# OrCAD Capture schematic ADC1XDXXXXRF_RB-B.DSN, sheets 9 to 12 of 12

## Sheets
9 FPGA1: size C; block B7
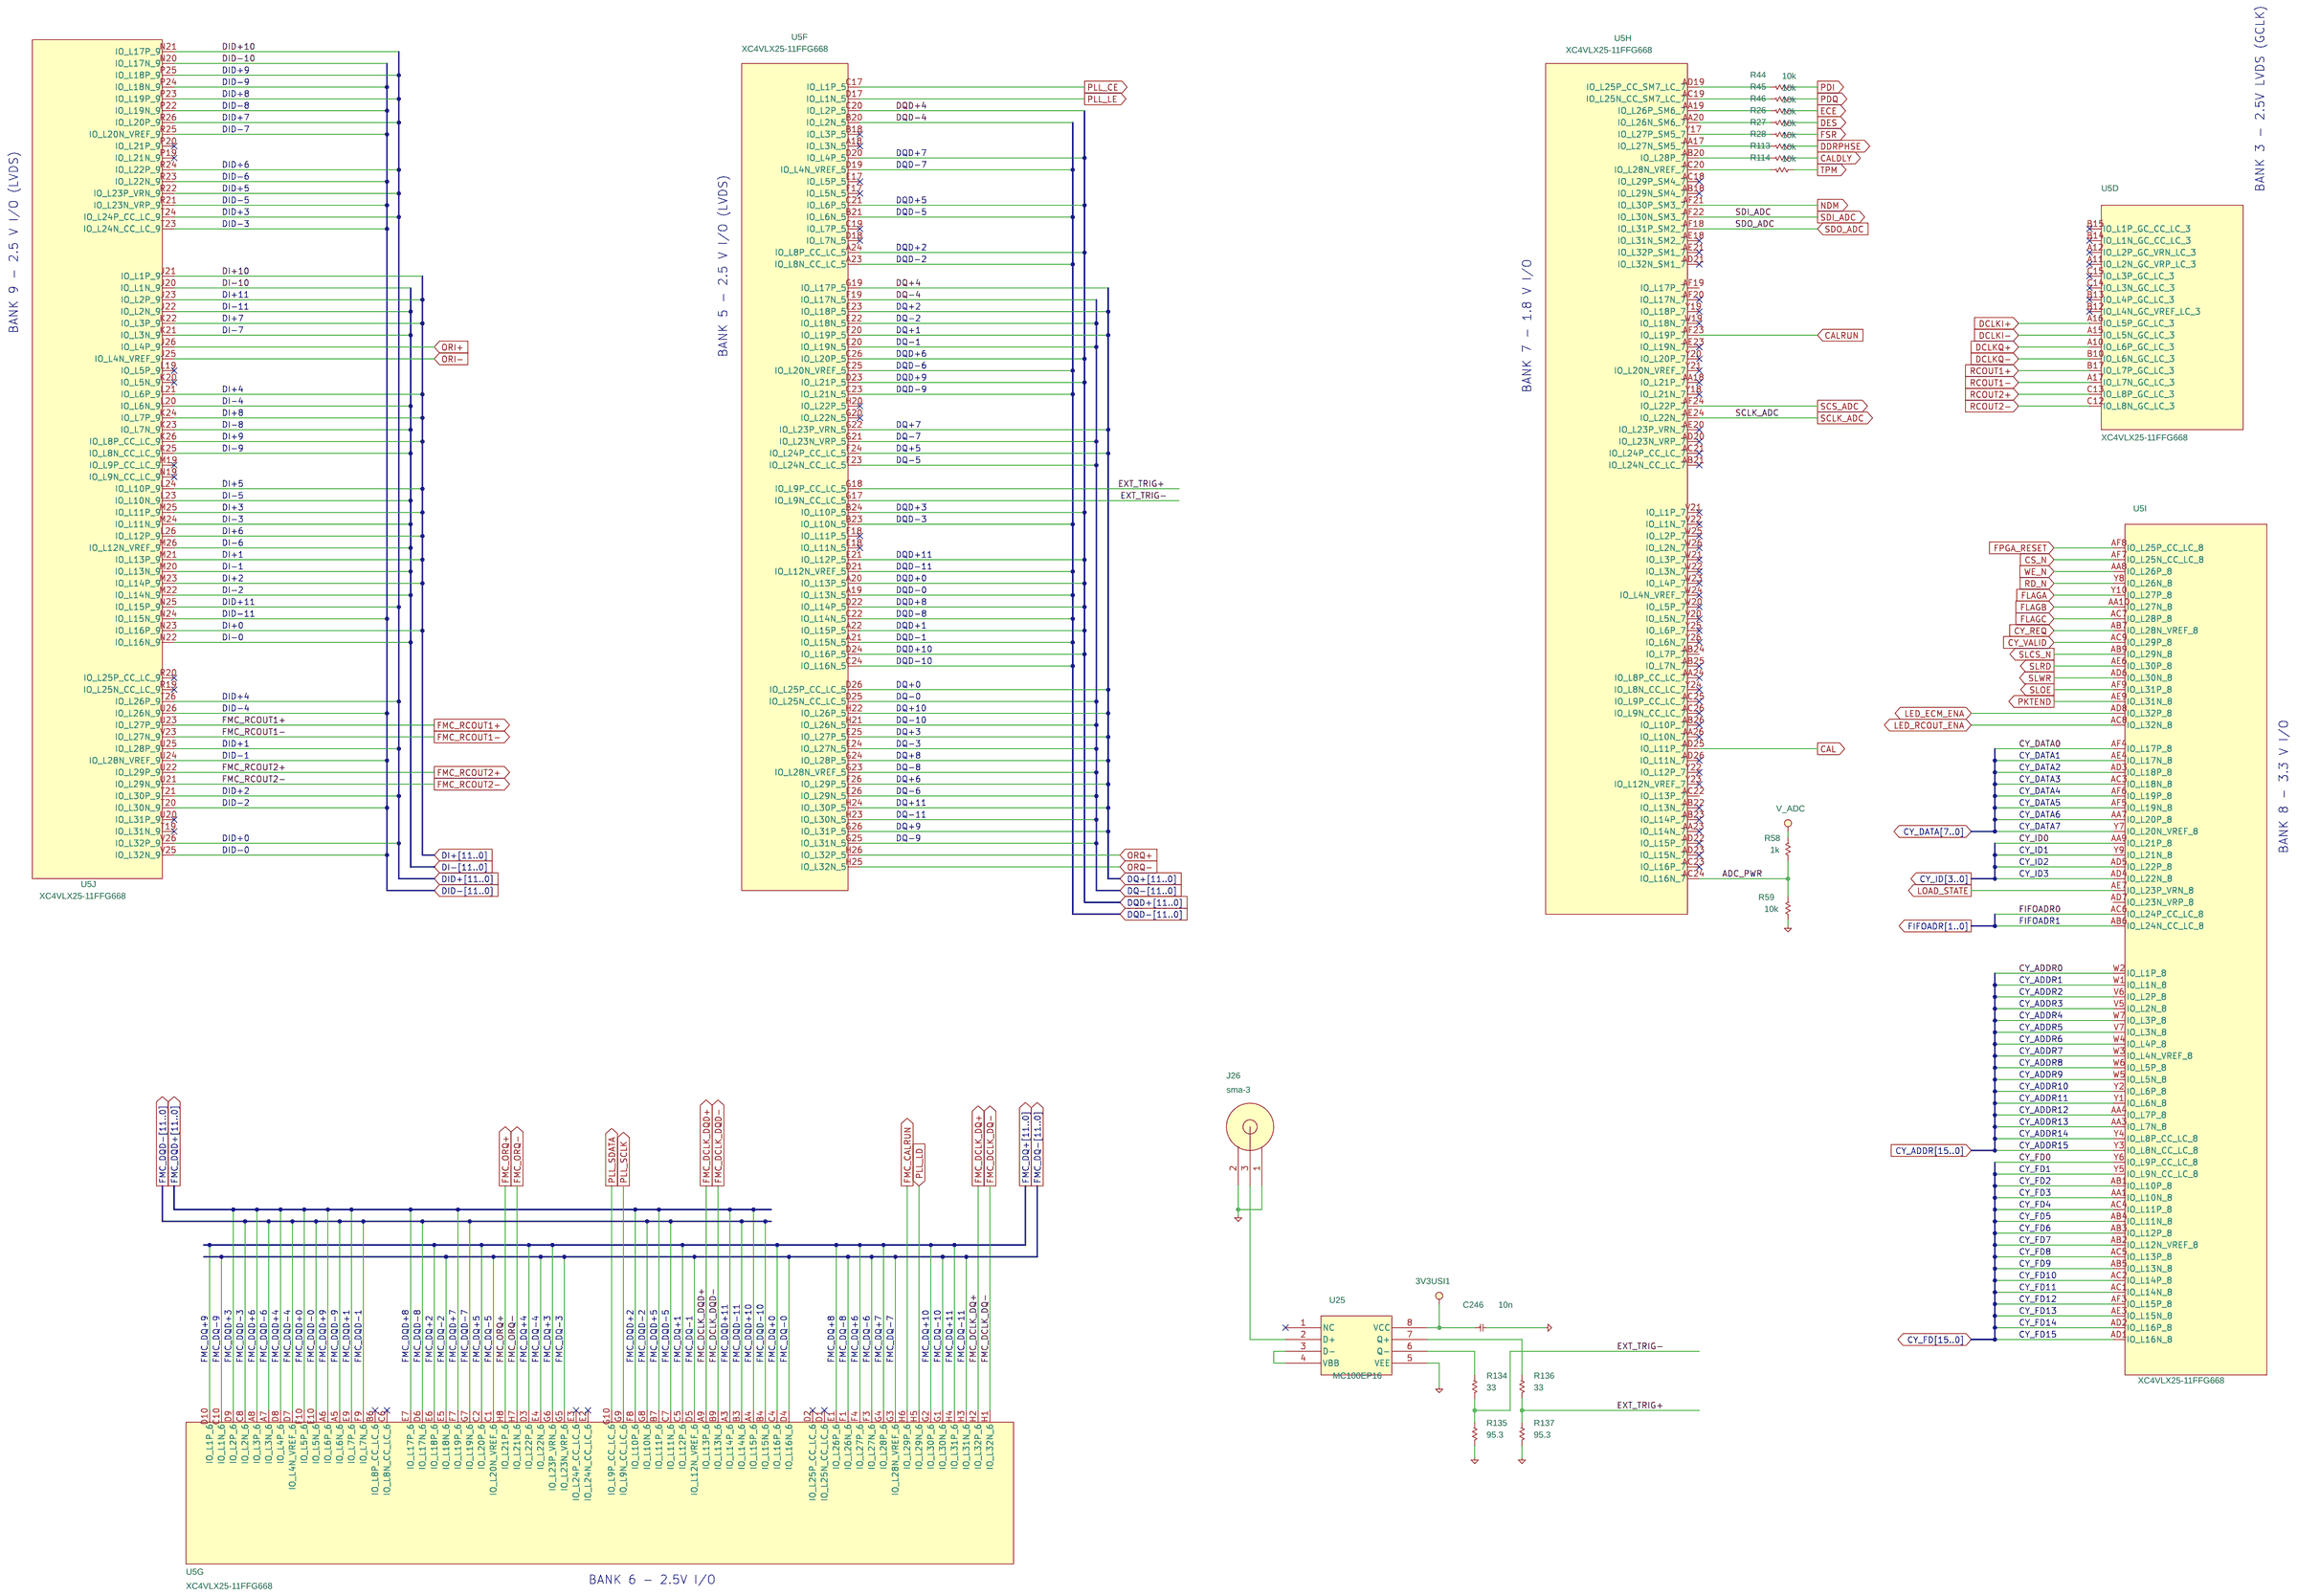
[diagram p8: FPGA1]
10 FPGA2: size C; block B7
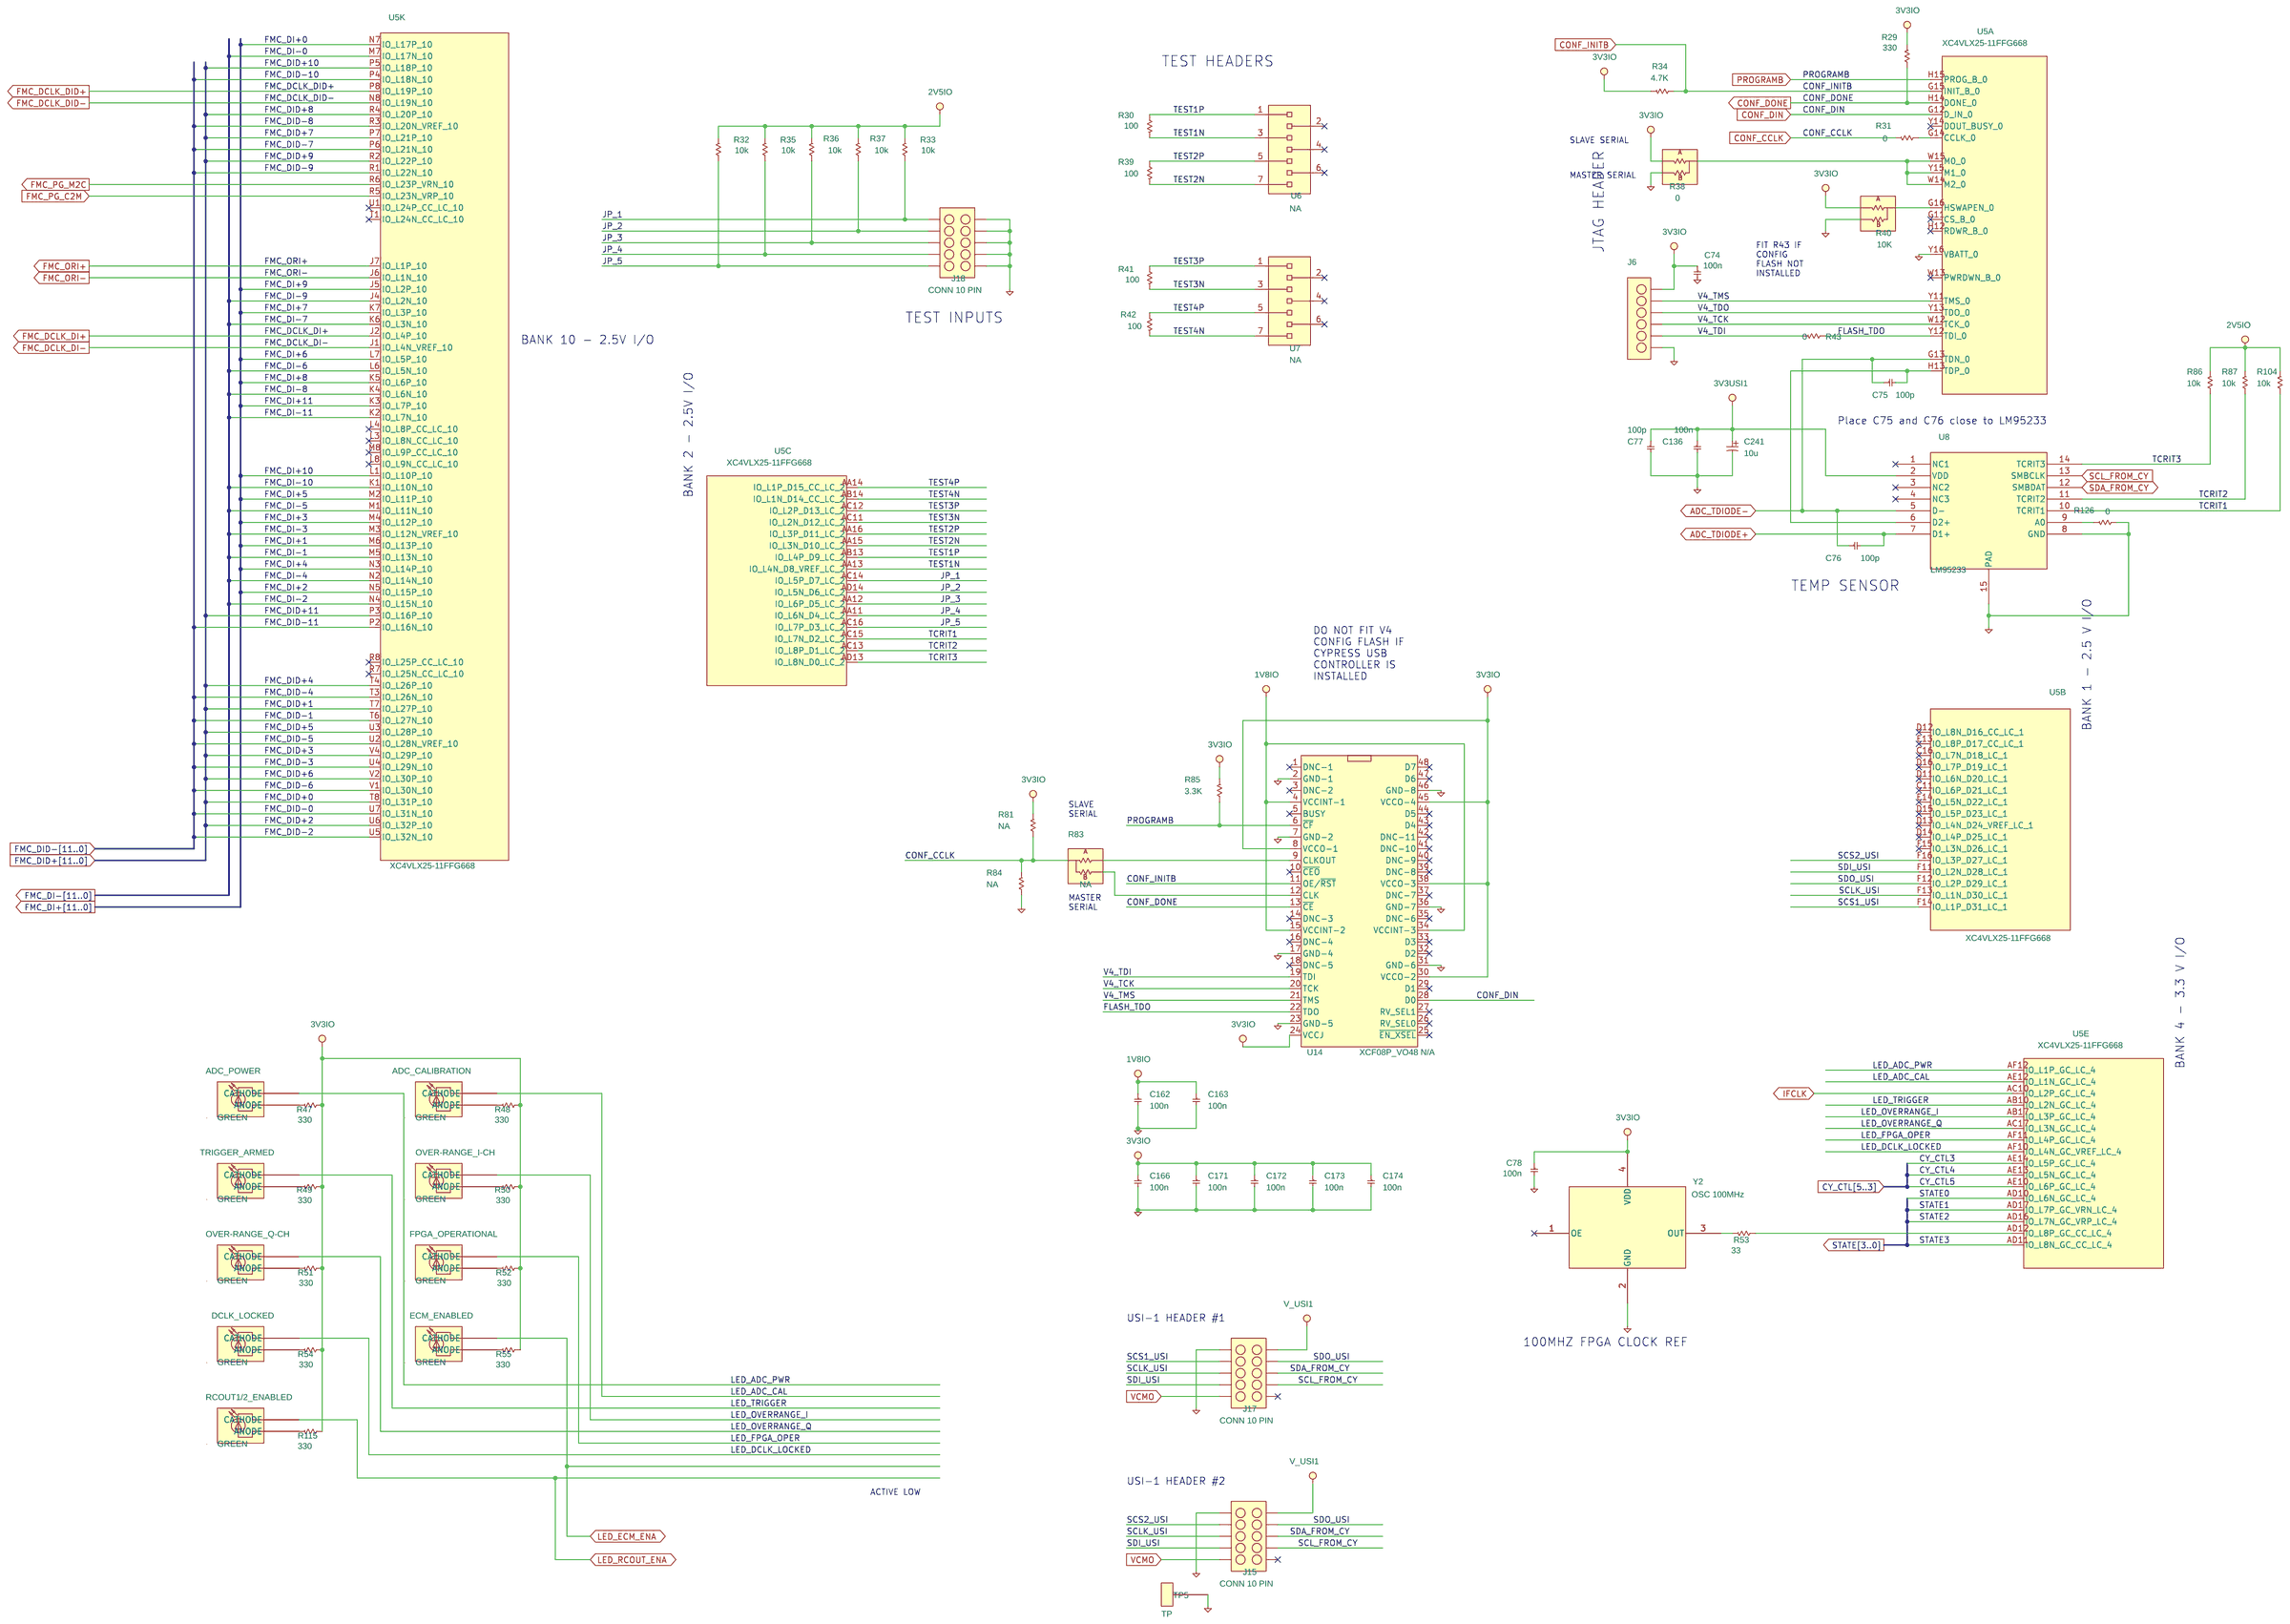
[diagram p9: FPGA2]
11 FPGA3: size C; block B7
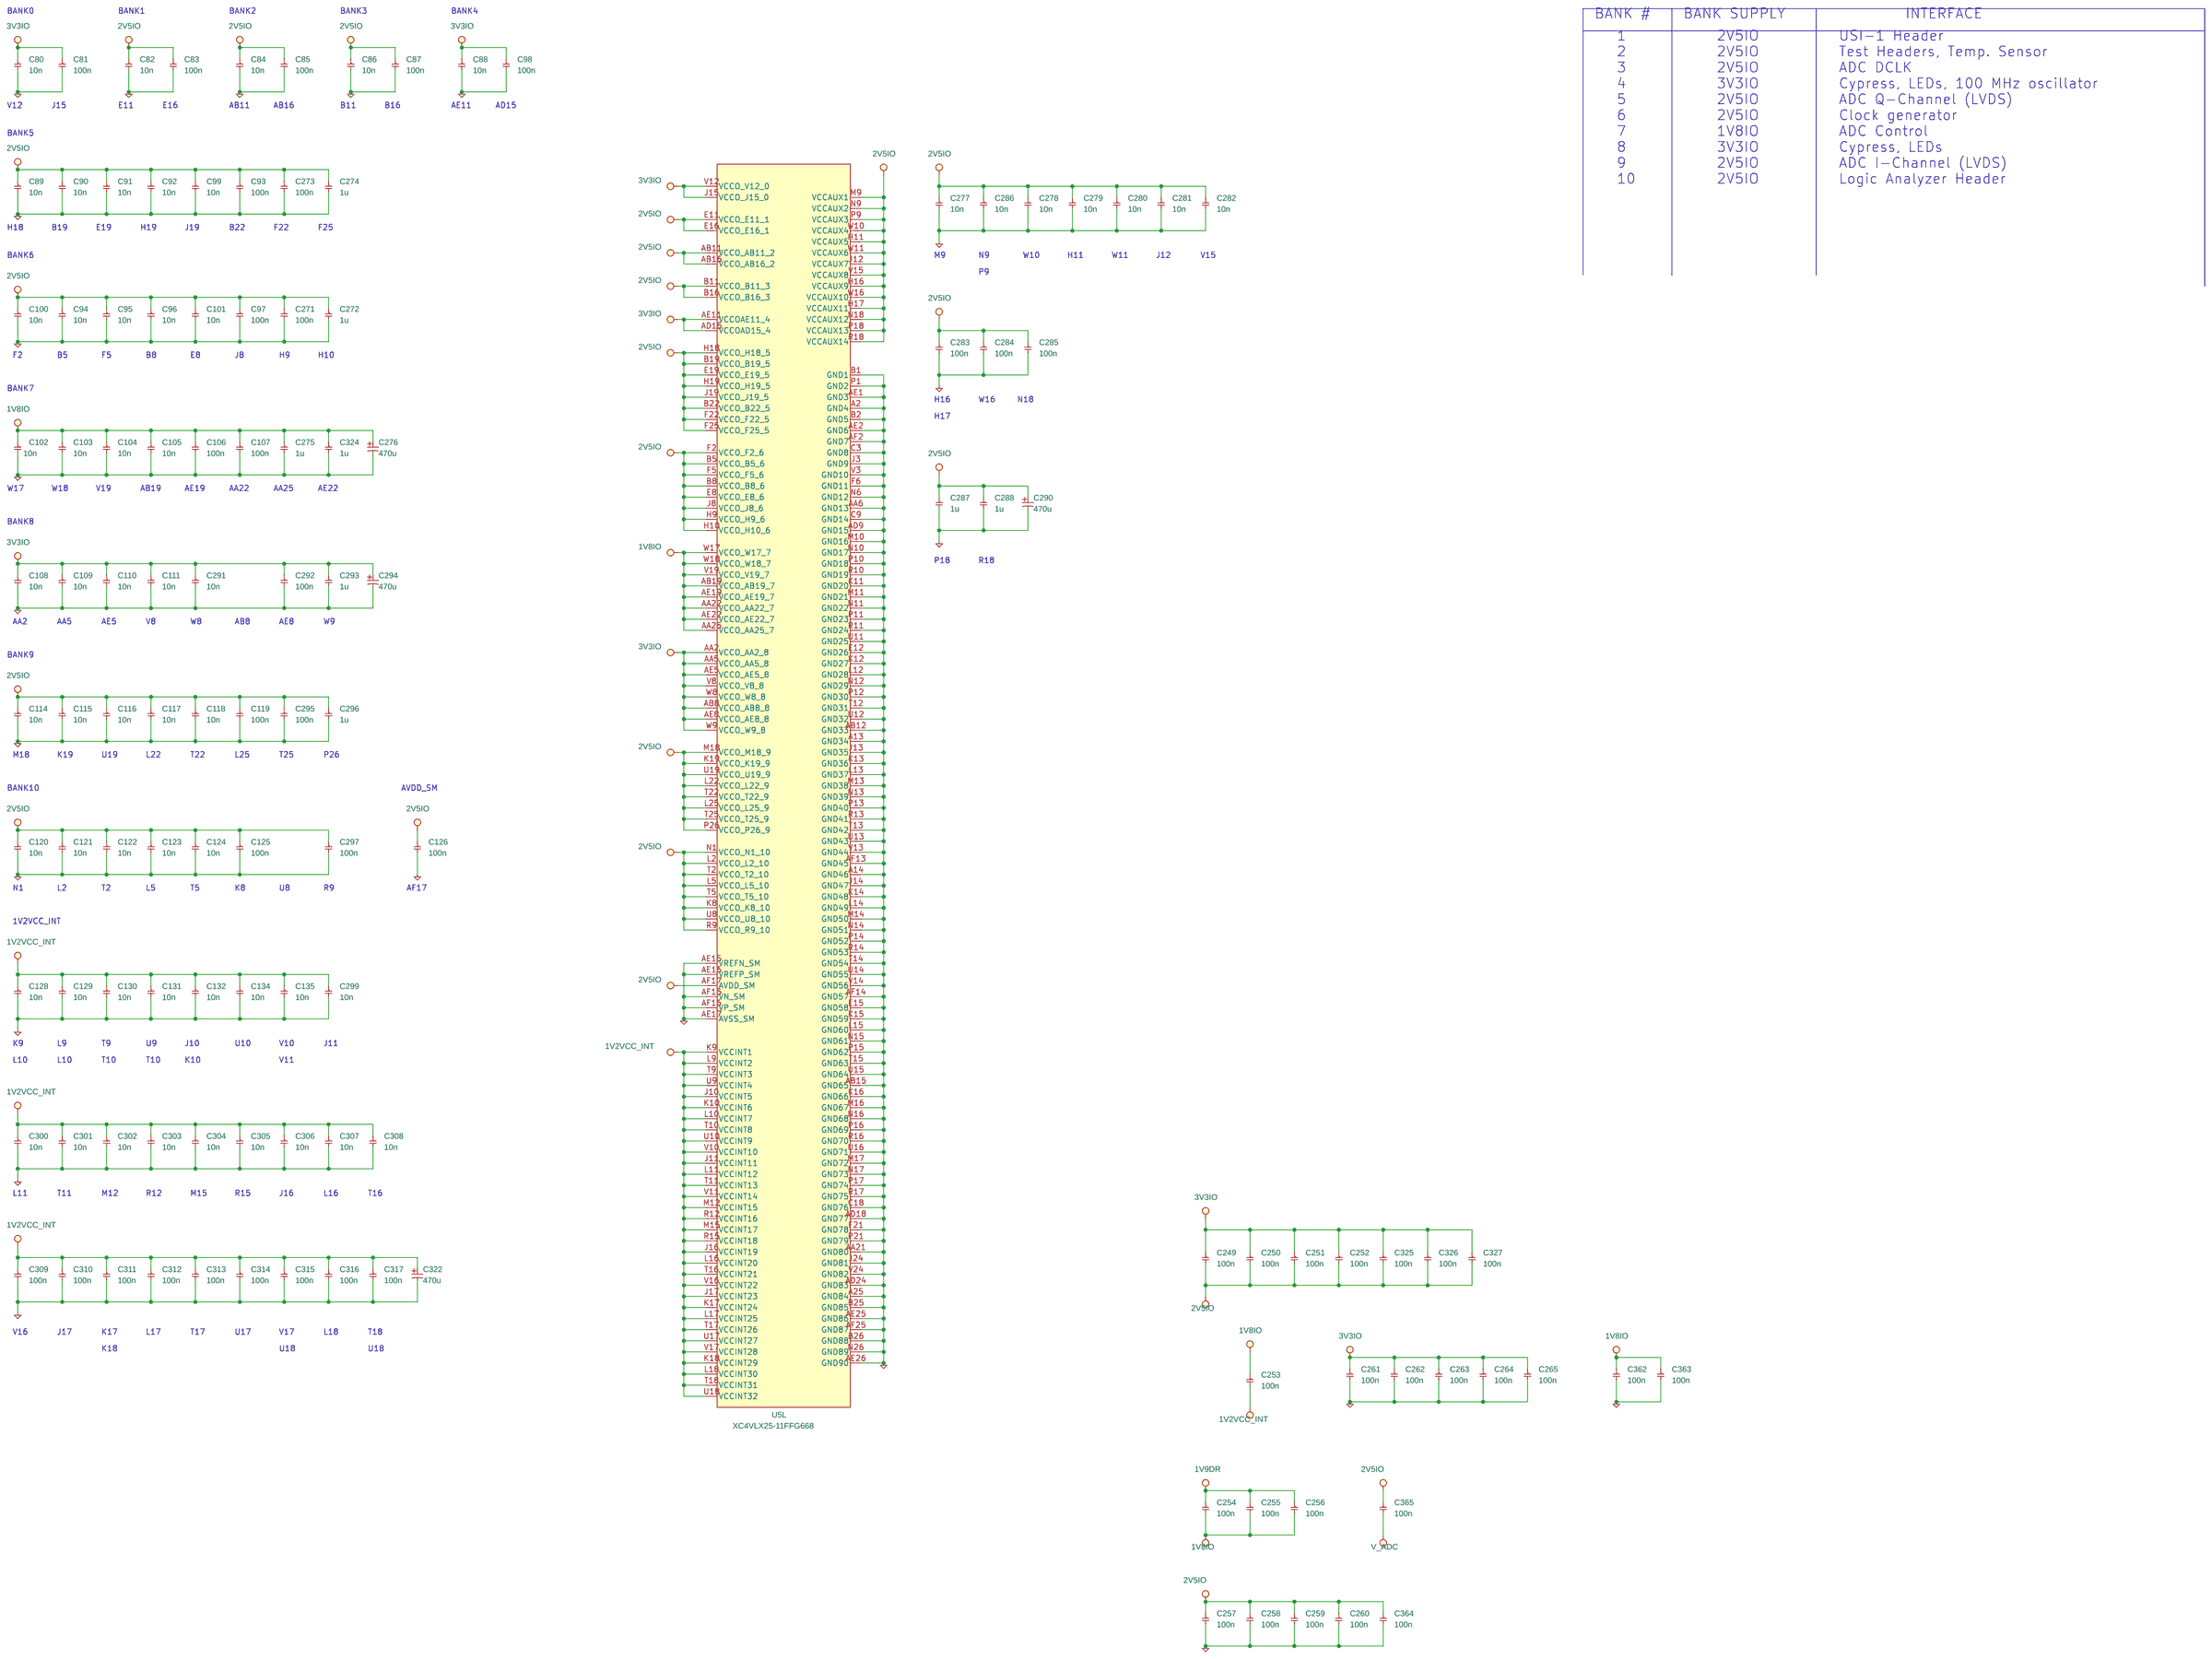
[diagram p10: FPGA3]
12 Front End: size C; block B6
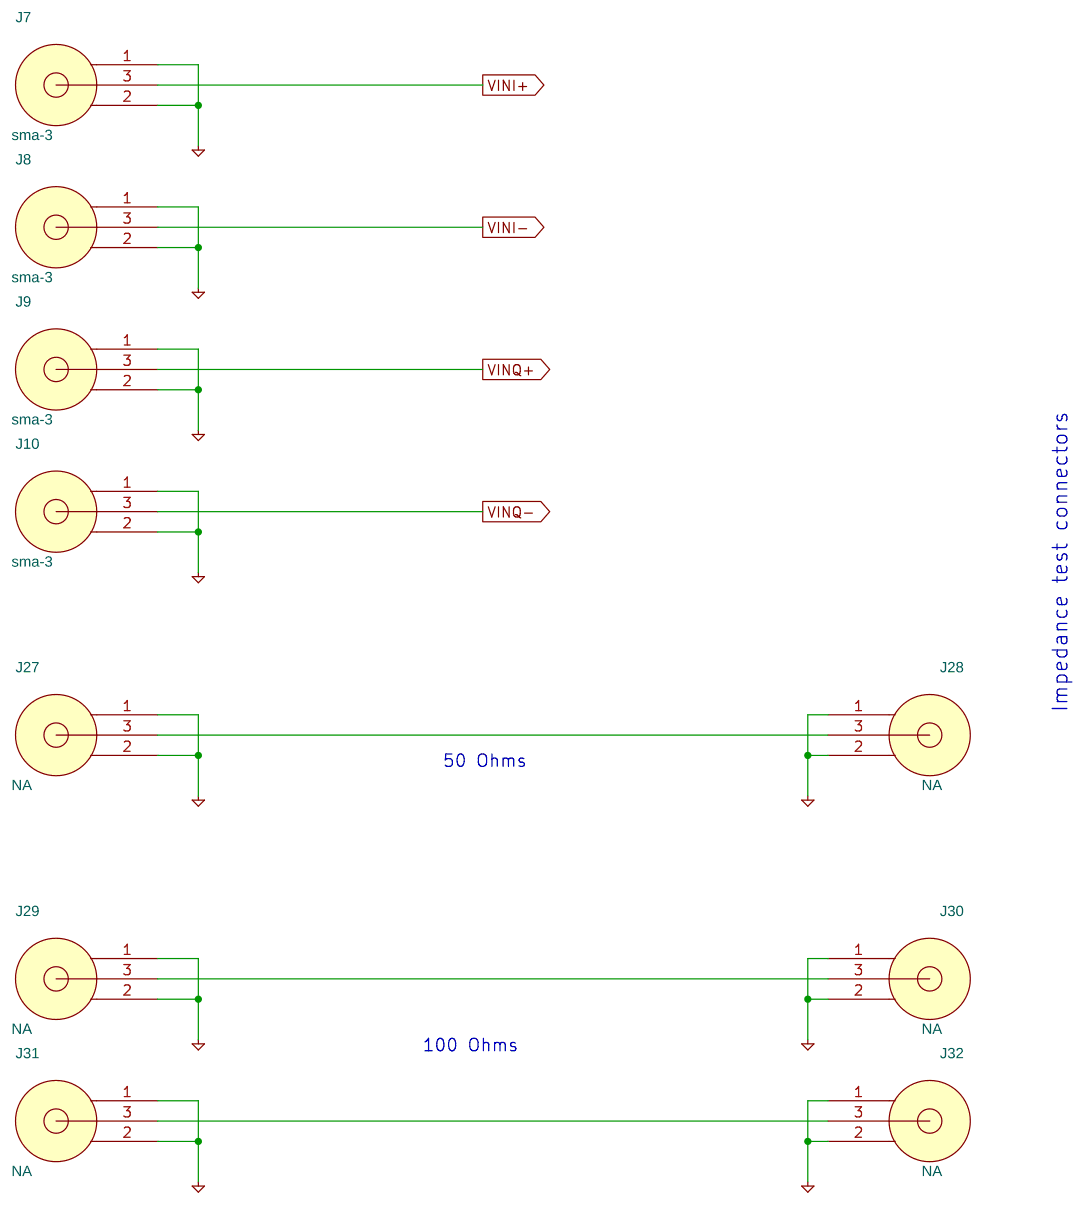
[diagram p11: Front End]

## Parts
sheet FPGA1
C246  10n  [c0402]
J26  sma-3  [RF_SMA_END_LAUNCH]
R26  10k  [r0603]
R27  10k  [r0603]
R28  10k  [r0603]
R44  10k  [r0603]
R45  10k  [r0603]
R46  10k  [r0603]
R58  1k  [r0603]
R59  10k  [r0603]
R113  10k  [r0603]
R114  10k  [r0603]
R134  33  [r0603]
R135  95.3  [r0603]
R136  33  [r0603]
R137  95.3  [r0603]
U5  XC4VLX25-11FFG668  [bga_668_27x27_1p0]  (sections A,B,C,D,E,F,G,H,I,J,K,L)
U25  MC100EP16  [TSSOP8_65M_WG4P9_L3]
sheet FPGA2
ADC_CALIBRATION  GREEN  [r1206]
ADC_POWER  GREEN  [r1206]
C74  100n  [c0603]
C75  100p  [c0402]
C76  100p  [c0402]
C77  100p  [c0402]
C78  100n  [c0603]
C136  100n  [c0603]
C162  100n  [c0603]
C163  100n  [c0603]
C166  100n  [c0603]
C171  100n  [c0603]
C172  100n  [c0603]
C173  100n  [c0603]
C174  100n  [c0603]
C241  10u  [c0805]
DCLK_LOCKED  GREEN  [r1206]
ECM_ENABLED  GREEN  [r1206]
FPGA_OPERATIONAL  GREEN  [r1206]
J6  CONN 6 PIN SINGLE ROW  [SHDR6X1]
J15  CONN 10 PIN  [th_10_hdr2x5_m_str_100]
J17  CONN 10 PIN  [th_10_hdr2x5_m_str_100]
J18  CONN 10 PIN  [th_10_hdr2x5_m_str_100]
OVER-RANGE_I-CH  GREEN  [r1206]
OVER-RANGE_Q-CH  GREEN  [r1206]
R29  330  [r0603]
R30  100  [r0603]
R31  0  [r0603]
R32  10k  [r0603]
R33  10k  [r0603]
R34  4.7K  [r0603]
R35  10k  [r0603]
R36  10k  [r0603]
R37  10k  [r0603]
R38  0  [0603_TRIPAD_1_to_2]
R39  100  [r0603]
R40  10K  [0603_TRIPAD_1_to_2]
R41  100  [r0603]
R42  100  [r0603]
R43  0  [r0603]
R47  330  [r0603]
R48  330  [r0603]
R49  330  [r0603]
R50  330  [r0603]
R51  330  [r0603]
R52  330  [r0603]
R53  33  [r0603]
R54  330  [r0603]
R55  330  [r0603]
R81  NA  [r0603]
R83  NA  [0603_TRIPAD]
R84  NA  [r0603]
R85  3.3K  [r0603]
R86  10k  [r0603]
R87  10k  [r0603]
R104  10k  [r0603]
R115  330  [r0603]
R126  0  [r0603]
RCOUT1/2_ENABLED  GREEN  [r1206]
TP5  TP  [tp40]
TRIGGER_ARMED  GREEN  [r1206]
U6  NA  [sm_7pin_ftr]
U7  NA  [sm_7pin_ftr]
U8  LM95233  [LLP14_p5mm_4x4_ep]
U14  XCF08P_VO48 N/A  [TSSOP48_50M_WG20_L12]
Y2  OSC 100MHz  [osc_100m_5x7]
sheet FPGA3
C80  10n  [c0402_no_ss]
C81  100n  [c0402_no_ss]
C82  10n  [c0402_no_ss]
C83  100n  [c0402_no_ss]
C84  10n  [c0402_no_ss]
C85  100n  [c0402_no_ss]
C86  10n  [c0402_no_ss]
C87  100n  [c0402_no_ss]
C88  10n  [c0402_no_ss]
C89  10n  [c0402_no_ss]
C90  10n  [c0402_no_ss]
C91  10n  [c0402_no_ss]
C92  10n  [c0402_no_ss]
C93  100n  [c0402_no_ss]
C94  10n  [c0402_no_ss]
C95  10n  [c0402_no_ss]
C96  10n  [c0402_no_ss]
C97  100n  [c0402_no_ss]
C98  100n  [c0402_no_ss]
C99  10n  [c0402_no_ss]
C100  10n  [c0402_no_ss]
C101  10n  [c0402_no_ss]
C102  10n  [c0402_no_ss]
C103  10n  [c0402_no_ss]
C104  10n  [c0402_no_ss]
C105  10n  [c0402_no_ss]
C106  100n  [c0402_no_ss]
C107  100n  [c0402_no_ss]
C108  10n  [c0402_no_ss]
C109  10n  [c0402_no_ss]
C110  10n  [c0402_no_ss]
C111  10n  [c0402_no_ss]
C114  10n  [c0402_no_ss]
C115  10n  [c0402_no_ss]
C116  10n  [c0402_no_ss]
C117  10n  [c0402_no_ss]
C118  10n  [c0402_no_ss]
C119  100n  [c0402_no_ss]
C120  10n  [c0402_no_ss]
C121  10n  [c0402_no_ss]
C122  10n  [c0402_no_ss]
C123  10n  [c0402_no_ss]
C124  10n  [c0402_no_ss]
C125  100n  [c0402_no_ss]
C126  100n  [c0402_no_ss]
C128  10n  [c0402_no_ss]
C129  10n  [c0402_no_ss]
C130  10n  [c0402_no_ss]
C131  10n  [c0402_no_ss]
C132  10n  [c0402_no_ss]
C134  10n  [c0402_no_ss]
C135  10n  [c0402_no_ss]
C249  100n  [c0402]
C250  100n  [c0402]
C251  100n  [c0402]
C252  100n  [c0402]
C253  100n  [c0402_no_ss]
C254  100n  [c0402]
C255  100n  [c0402]
C256  100n  [c0402]
C257  100n  [c0402]
C258  100n  [c0402]
C259  100n  [c0402]
C260  100n  [c0402_no_ss]
C261  100n  [c0402]
C262  100n  [c0402]
C263  100n  [c0402]
C264  100n  [c0402]
C265  100n  [c0402]
C271  100n  [c0402_no_ss]
C272  1u  [c0402_no_ss]
C273  100n  [c0402_no_ss]
C274  1u  [c0402_no_ss]
C275  1u  [c0402_no_ss]
C276  470u  [cap_c-case]
C277  10n  [c0402_no_ss]
C278  10n  [c0402_no_ss]
C279  10n  [c0402_no_ss]
C280  10n  [c0402_no_ss]
C281  10n  [c0402_no_ss]
C282  10n  [c0402_no_ss]
C283  100n  [c0402_no_ss]
C284  100n  [c0402_no_ss]
C285  100n  [c0402_no_ss]
C286  10n  [c0402_no_ss]
C287  1u  [c0402_no_ss]
C288  1u  [c0402_no_ss]
C290  470u  [cap_c-case]
C291  10n  [c0402_no_ss]
C292  100n  [c0402_no_ss]
C293  1u  [c0402_no_ss]
C294  470u  [cap_c-case]
C295  100n  [c0402_no_ss]
C296  1u  [c0402_no_ss]
C297  100n  [c0402_no_ss]
C299  10n  [c0402_no_ss]
C300  10n  [c0402_no_ss]
C301  10n  [c0402_no_ss]
C302  10n  [c0402_no_ss]
C303  10n  [c0402_no_ss]
C304  10n  [c0402_no_ss]
C305  10n  [c0402_no_ss]
C306  10n  [c0402_no_ss]
C307  10n  [c0402_no_ss]
C308  10n  [c0402_no_ss]
C309  100n  [c0402_no_ss]
C310  100n  [c0402_no_ss]
C311  100n  [c0402_no_ss]
C312  100n  [c0402_no_ss]
C313  100n  [c0402_no_ss]
C314  100n  [c0402_no_ss]
C315  100n  [c0402_no_ss]
C316  100n  [c0402_no_ss]
C317  100n  [c0402_no_ss]
C322  470u  [cap_c-case]
C324  1u  [c0402_no_ss]
C325  100n  [c0402]
C326  100n  [c0402]
C327  100n  [c0402]
C362  100n  [c0402]
C363  100n  [c0402]
C364  100n  [c0402_no_ss]
C365  100n  [c0402_no_ss]
sheet Front End
J7  sma-3  [RF_SMA_END_LAUNCH]
J8  sma-3  [RF_SMA_END_LAUNCH]
J9  sma-3  [RF_SMA_END_LAUNCH]
J10  sma-3  [RF_SMA_END_LAUNCH]
J27  NA  [RF_SMA_END_LAUNCH]
J28  NA  [RF_SMA_END_LAUNCH]
J29  NA  [RF_SMA_END_LAUNCH]
J30  NA  [RF_SMA_END_LAUNCH]
J31  NA  [RF_SMA_END_LAUNCH]
J32  NA  [RF_SMA_END_LAUNCH]

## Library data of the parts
C80 C82 C84 C86 C88-C92 C94-C96 C99-C105 C108-C111 C114-C118 C120-C124 C128-C132 C134 C135 C246 C277-C282 C286 C291 C299-C308 = C-NON-POL: Distributed by: Digikey; Distributor Part #: 445-1260-1-ND; Manufactured by: TDK Corporation; Part Description: CAP CER 10000PF 25V 10% X7R 0402; Part Number: C1005X7R1E103K
J7-J10 J26 = sma-3_0: Distributed by: Digikey; Distributor Part #: J658-ND; Manufactured by: Emerson Network Power Connectivity Solutions; Part Description: CONN JACK END LAUNCH PC GOLD SMA; Part Number: 142-0701-851
R26-R28 R32 R33 R35-R37 R44-R46 R59 R86 R87 R104 R113 R114 = RESISTOR: Distributed by: Digikey; Distributor Part #: P10KGCT-ND; Manufactured by: Panasonic; Part Description: RES 10K OHM 1/10W 5% 0603 SMD; Part Number: ERJ-3GEYJ103V
R58 = RESISTOR: Distributed by: Digikey; Distributor Part #: P1.0KGCT-ND; Manufactured by: Panasonic; Part Description: RES 1.0K OHM 1/10W 5% 0603 SMD; Part Number: ERJ-3GEYJ102V
R53 R134 R136 = RESISTOR: Distributed by: Digikey; Distributor Part #: P33GCT-ND; Manufactured by: Panasonic; Part Description: RES 33 OHM 1/10W 5% 0603 SMD; Part Number: ERJ-3GEYJ330V
R135 R137 = RESISTOR: Distributed by: Digikey; Distributor Part #: P95.3HCT-ND; Manufactured by: Panasonic; Part Description: RES 95.3 OHM 1/10W 1% 0603 SMD; Part Number: ERJ-3EKF95R3V
U5 = XC4VLX25-11FFG668__3: Distributed by: NuHorizons; Manufactured by: Xilinx; Part Description: FPGA VIRTEX-4 FG668 -11
U25 = MC10EP16: Distributed by: Digikey; Distributor Part #: MC100EP16DTGOS-ND; Manufactured by: On Semiconductor; Part Description: IC RCVR/DRVR ECL DIFF 5V 8TSSOP; Part Number: MC100EP16DTG
ADC_CALIBRATION ADC_POWER DCLK_LOCKED ECM_ENABLED FPGA_OPERATIONAL OVER-RANGE_I-CH OVER-RANGE_Q-CH RCOUT1/2_ENABLED TRIGGER_ARMED = LED_SNGLE_PANEL: Distributed by: Digikey; Distributor Part #: 67-1357-1-ND; Manufactured by: Lumex; Part Description: LED 565NM WTR CLR GREEN 1206 SMD; Part Number: SML-LX1206GC-TR
C74 C78 C136 C162 C163 C166 C171-C174 = C-NON-POL: Distributed by: Digikey; Distributor Part #: 445-1317-1-ND; Manufactured by: TDK Corporation; Part Description: CAP CER 0.1UF 16V 10% X7R 0603; Part Number: C1608X7R1C104K
C75-C77 = C-NON-POL: Distributed by: Digikey; Distributor Part #: 399-3194-1-ND; Manufactured by: Kemet; Part Description: CAP CER 100PF 50V 5% NP0 0402; Part Number: C0402C101J5GACTU
C241 = C-POLARISED: Distributed by: Digikey; Distributor Part #: 445-1363-2-ND; Manufactured by: TDK; Part Description: CAP CER 10UF 6.3V 20% X5R 0805; Part Number: C2012X5R0J106M/1.25
J6 = CONN_6_PIN_SINGLE_ROW: Comment: BROKEN TO SIZE; Distributed by: Digikey; Distributor Part #: S1012E-36-ND; Manufactured by: Sullins Connector Solutions; Part Description: CONN HEADER .100 SINGL STR 36POS; Part Number: PEC36SAAN
J15 J17 J18 = CONN_10_PIN_2mm_SMT_DUAL_ROW: Comment: BROKEN TO SIZE; Distributed by: Digikey; Distributor Part #: S2012E-36-ND; Manufactured by: Sullins Connector Solutions; Part Description: CONN HEADER .100 DUAL STR 72POS; Part Number: PEC36DAAN
R29 R47-R52 R54 R55 R115 = RESISTOR: Distributed by: Digikey; Distributor Part #: P330GTR-ND; Manufactured by: Panasonic; Part Description: RES 330 OHM 1/10W 5% 0603 SMD; Part Number: ERJ-3GEYJ331V
R30 R39 R41 R42 = RESISTOR: Distributed by: Digikey; Distributor Part #: P100GCT-ND; Manufactured by: Panasonic; Part Description: RES 100 OHM 1/10W 5% 0603 SMD; Part Number: ERJ-3GEYJ101V
R31 R43 R126 = RESISTOR: Distributed by: Digikey; Distributor Part #: P0.0GCT-ND; Manufactured by: Panasonic; Part Description: RES 0 OHM 1/10W 5% 0603 SMD; Part Number: ERJ-3GEY0R00V
R34 = RESISTOR: Distributed by: Digikey; Distributor Part #: P4.7KGCT-ND; Manufactured by: Panasonic; Part Description: RES 4.7K OHM 1/10W 5% 0603 SMD; Part Number: ERJ-3GEYJ472V
R38 = RESISTOR_TRIPAD: Distributed by: Digikey; Distributor Part #: P0.0GTR-ND; Manufactured by: Panasonic; Part Description: RES 0 OHM 1/10W 5% 0603 SMD; Part Number: ERJ-3GEY0R00V
R40 = RESISTOR_TRIPAD: Distributed by: Digikey; Distributor Part #: P10KGTR-ND; Manufactured by: Panasonic; Part Description: RES 10K OHM 1/10W 5% 0603 SMD; Part Number: ERJ-3GEYJ103V
R81 R84 = RESISTOR
R83 = RESISTOR_TRIPAD
R85 = RESISTOR: Distributed by: Digikey; Distributor Part #: P3.3KGTR-ND; Manufactured by: Panasonic; Part Description: RES 3.3K OHM 1/10W 5% 0603 SMD; Part Number: ERJ-3GEYJ332V
TP5 = TEST_POINT: Comment: BROKEN TO SIZE; Distributed by: Digikey; Distributor Part #: S1012E-36-ND; Manufactured by: Sullins Connector Solutions; Part Description: CONN HEADER .100 SINGL STR 36POS; Part Number: PEC36SAAN
U6 U7 = 2MM_7PIN_HEADER
U8 = LM95233: Distributed by: Digikey; Distributor Part #: LM95233CISDCT-ND; Manufactured by: Texas Instruments; Part Description: IC TEMP SENSOR DUAL REMOTE 14LLP; Part Number: LM95233CISD/NOPB
U14 = XCF08P_VO48_1: Manufactured by: Xilinx; Part Description: Xilinx Configuration Flash ROM (8Mb) JTAG; Part Number: XCF08P VO48 C
Y2 = OSC-SM: Distributed by: Pletronics; Distributor Part #: SM7745DSV-100.00M; Manufactured by: Pletronics; Part Description: OSC CLOCK 100.0000 MHZ 3.3V SMD; Part Number: SM7745DSV-100.00M
C81 C83 C85 C87 C93 C97 C98 C106 C107 C119 C125 C126 C253 C271 C273 C283-C285 C292 C295 C297 C309-C317 = C-NON-POL: Distributed by: Digikey; Distributor Part #: PCC2146TR-ND; Manufactured by: Panasonic; Part Description: Capacitor, SMT 0402, MLC, X5R, 10%, 10V; Part Number: ECJ-0EB1A104K
C249-C252 C254-C265 C325-C327 C362-C365 = C-NON-POL: Distributed by: Digikey; Distributor Part #: 478-1129-1-ND; Manufactured by: AVX Corporation; Part Description: CAP CER 0.1UF 10% 10V X5R 0402; Part Number: 0402ZD104KAT2A
C272 C274 C275 C287 C288 C293 C296 C324 = C-NON-POL: Distributed by: Digikey; Distributor Part #: 399-4873-1-ND; Manufactured by: Kemet; Part Description: CAP CER 1UF 6.3V 10% X5R 0402; Part Number: C0402C105K9PACTU
C276 C290 C294 C322 = C-POLARISED: Distributed by: Digikey; Distributor Part #: 478-4772-1-ND; Manufactured by: AVX Corporation; Part Description: CAP TANT 470UF 4V 10% 2312; Part Number: TAJC477K004RNJ
J27-J32 = sma-3_0

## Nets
1V2VCC_INT: C128.1 C129.1 C130.1 C131.1 C132.1 C134.1 C135.1 C253.2 C299.1 C300.1 C301.1 C302.1 C303.1 C304.1 C305.1 C306.1 C307.1 C308.1 C309.1 C310.1 C311.1 C312.1 C313.1 C314.1 C315.1 C316.1 C317.1 C322.1(POS) U5.J10(VCCINT5) U5.J11(VCCINT11) U5.J16(VCCINT19) U5.J17(VCCINT23) U5.K9(VCCINT1) U5.K10(VCCINT6) U5.K17(VCCINT24) U5.K18(VCCINT29) U5.L9(VCCINT2) U5.L10(VCCINT7) U5.L11(VCCINT12) U5.L16(VCCINT20) U5.L17(VCCINT25) U5.L18(VCCINT30) U5.M12(VCCINT15) U5.M15(VCCINT17) U5.R12(VCCINT16) U5.R15(VCCINT18) U5.T9(VCCINT3) U5.T10(VCCINT8) U5.T11(VCCINT13) U5.T16(VCCINT21) U5.T17(VCCINT26) U5.T18(VCCINT31) U5.U9(VCCINT4) U5.U10(VCCINT9) U5.U17(VCCINT27) U5.U18(VCCINT32) U5.V10(VCCINT10) U5.V11(VCCINT14) U5.V16(VCCINT22) U5.V17(VCCINT28) ; also on sheet 6
1V8IO: C102.1 C103.1 C104.1 C105.1 C106.1 C107.1 C162.1 C163.1 C253.1 C254.2 C255.2 C256.2 C275.1 C276.1(POS) C324.1 C362.1 C363.1 U5.AA22(VCCO_AA22_7) U5.AA25(VCCO_AA25_7) U5.AB19(VCCO_AB19_7) U5.AE19(VCCO_AE19_7) U5.AE22(VCCO_AE22_7) U5.V19(VCCO_V19_7) U5.W17(VCCO_W17_7) U5.W18(VCCO_W18_7) U14.4(VCCINT-1) U14.15(VCCINT-2) U14.34(VCCINT-3) ; also on sheet 3 6
1V9DR: C254.1 C255.1 C256.1 ; also on sheet 3
2V5IO: C82.1 C83.1 C84.1 C85.1 C86.1 C87.1 C89.1 C90.1 C91.1 C92.1 C93.1 C94.1 C95.1 C96.1 C97.1 C99.1 C100.1 C101.1 C114.1 C115.1 C116.1 C117.1 C118.1 C119.1 C120.1 C121.1 C122.1 C123.1 C124.1 C125.1 C126.1 C249.2 C250.2 C251.2 C252.2 C257.1 C258.1 C259.1 C260.1 C271.1 C272.1 C273.1 C274.1 C277.1 C278.1 C279.1 C280.1 C281.1 C282.1 C283.1 C284.1 C285.1 C286.1 C287.1 C288.1 C290.1(POS) C295.1 C296.1 C297.1 C325.2 C326.2 C327.2 C364.1 C365.1 R32.1 R33.1 R35.1 R36.1 R37.1 R86.1 R87.1 R104.1 U5.AB11(VCCO_AB11_2) U5.AB16(VCCO_AB16_2) U5.AF17(AVDD_SM) U5.B5(VCCO_B5_6) U5.B8(VCCO_B8_6) U5.B11(VCCO_B11_3) U5.B16(VCCO_B16_3) U5.B19(VCCO_B19_5) U5.B22(VCCO_B22_5) U5.E8(VCCO_E8_6) U5.E11(VCCO_E11_1) U5.E16(VCCO_E16_1) U5.E19(VCCO_E19_5) U5.F2(VCCO_F2_6) U5.F5(VCCO_F5_6) U5.F22(VCCO_F22_5) U5.F25(VCCO_F25_5) U5.H9(VCCO_H9_6) U5.H10(VCCO_H10_6) U5.H11(VCCAUX5) U5.H16(VCCAUX9) U5.H17(VCCAUX11) U5.H18(VCCO_H18_5) U5.H19(VCCO_H19_5) U5.J8(VCCO_J8_6) U5.J12(VCCAUX7) U5.J19(VCCO_J19_5) U5.K8(VCCO_K8_10) U5.K19(VCCO_K19_9) U5.L2(VCCO_L2_10) U5.L5(VCCO_L5_10) U5.L22(VCCO_L22_9) U5.L25(VCCO_L25_9) U5.M9(VCCAUX1) U5.M18(VCCO_M18_9) U5.N1(VCCO_N1_10) U5.N9(VCCAUX2) U5.N18(VCCAUX12) U5.P9(VCCAUX3) U5.P18(VCCAUX13) U5.P26(VCCO_P26_9) U5.R9(VCCO_R9_10) U5.R18(VCCAUX14) U5.T2(VCCO_T2_10) U5.T5(VCCO_T5_10) U5.T22(VCCO_T22_9) U5.T25(VCCO_T25_9) U5.U8(VCCO_U8_10) U5.U19(VCCO_U19_9) U5.V15(VCCAUX8) U5.W10(VCCAUX4) U5.W11(VCCAUX6) U5.W16(VCCAUX10) ; also on sheet 4 6
3V3IO: C74.1 C78.1 C80.1 C81.1 C88.1 C98.1 C108.1 C109.1 C110.1 C111.1 C166.1 C171.1 C172.1 C173.1 C174.1 C249.1 C250.1 C251.1 C252.1 C261.1 C262.1 C263.1 C264.1 C265.1 C291.1 C292.1 C293.1 C294.1(POS) C325.1 C326.1 C327.1 J6.1 R29.1 R34.1 R38.1 R40.1 R47.2 R48.2 R49.2 R50.2 R51.2 R52.2 R54.2 R55.2 R81.1 R85.1 R115.2 U5.AA2(VCCO_AA2_8) U5.AA5(VCCO_AA5_8) U5.AB8(VCCO_AB8_8) U5.AD15(VCCOAD15_4) U5.AE5(VCCO_AE5_8) U5.AE8(VCCO_AE8_8) U5.AE11(VCCOAE11_4) U5.J15(VCCO_J15_0) U5.V8(VCCO_V8_8) U5.V12(VCCO_V12_0) U5.W8(VCCO_W8_8) U5.W9(VCCO_W9_8) U14.8(VCCO-1) U14.24(VCCJ) U14.30(VCCO-2) U14.38(VCCO-3) U14.45(VCCO-4) Y2.4(VDD) ; also on sheet 6
3V3USI1: C77.1 C136.1 C241.1(POS) C246.1 U8.2(VDD) U25.8(VCC) ; also on sheet 3 6
B7/V4_TCK: J6.4 U5.W12(TCK_0) U14.20(TCK)
B7/V4_TDI: J6.5 R43.1 U14.19(TDI)
B7/V4_TDO: J6.3 U5.Y13(TDO_0)
B7/V4_TMS: J6.2 U5.Y11(TMS_0) U14.21(TMS)
GND: C74.2 C77.2 C78.2 C80.2 C81.2 C82.2 C83.2 C84.2 C85.2 C86.2 C87.2 C88.2 C89.2 C90.2 C91.2 C92.2 C93.2 C94.2 C95.2 C96.2 C97.2 C98.2 C99.2 C100.2 C101.2 C102.2 C103.2 C104.2 C105.2 C106.2 C107.2 C108.2 C109.2 C110.2 C111.2 C114.2 C115.2 C116.2 C117.2 C118.2 C119.2 C120.2 C121.2 C122.2 C123.2 C124.2 C125.2 C126.2 C128.2 C129.2 C130.2 C131.2 C132.2 C134.2 C135.2 C136.2 C162.2 C163.2 C166.2 C171.2 C172.2 C173.2 C174.2 C241.2(NEG) C246.2 C257.2 C258.2 C259.2 C260.2 C261.2 C262.2 C263.2 C264.2 C265.2 C271.2 C272.2 C273.2 C274.2 C275.2 C276.2(NEG) C277.2 C278.2 C279.2 C280.2 C281.2 C282.2 C283.2 C284.2 C285.2 C286.2 C287.2 C288.2 C290.2(NEG) C291.2 C292.2 C293.2 C294.2(NEG) C295.2 C296.2 C297.2 C299.2 C300.2 C301.2 C302.2 C303.2 C304.2 C305.2 C306.2 C307.2 C308.2 C309.2 C310.2 C311.2 C312.2 C313.2 C314.2 C315.2 C316.2 C317.2 C322.2(NEG) C324.2 C362.2 C363.2 C364.2 J6.6 J7.1 J7.2 J8.1 J8.2 J9.1 J9.2 J10.1 J10.2 J15.1 J17.1 J18.2 J18.4 J18.6 J18.8 J18.10 J26.1 J26.2 J27.1 J27.2 J28.1 J28.2 J29.1 J29.2 J30.1 J30.2 J31.1 J31.2 J32.1 J32.2 R38.3 R40.3 R59.2 R84.2 R126.2 R135.2 R137.2 TP5.1 U5.A2(GND4) U5.A13(GND34) U5.A14(GND46) U5.A25(GND84) U5.AA6(GND13) U5.AA21(GND80) U5.AB12(GND33) U5.AB15(GND65) U5.AD9(GND15) U5.AD18(GND77) U5.AD24(GND83) U5.AE1(GND3) U5.AE2(GND6) U5.AE15(VREFN_SM) U5.AE16(VREFP_SM) U5.AE17(AVSS_SM) U5.AE25(GND86) U5.AE26(GND90) U5.AF2(GND7) U5.AF13(GND45) U5.AF14(GND57) U5.AF15(VN_SM) U5.AF16(VP_SM) U5.AF25(GND87) U5.B1(GND1) U5.B2(GND5) U5.B25(GND85) U5.B26(GND88) U5.C3(GND8) U5.C9(GND14) U5.C18(GND76) U5.E12(GND26) U5.E15(GND58) U5.F6(GND11) U5.F21(GND78) U5.J3(GND9) U5.J13(GND35) U5.J14(GND47) U5.J24(GND81) U5.K11(GND20) U5.K12(GND27) U5.K13(GND36) U5.K14(GND48) U5.K15(GND59) U5.K16(GND66) U5.L12(GND28) U5.L13(GND37) U5.L14(GND49) U5.L15(GND60) U5.M10(GND16) U5.M11(GND21) U5.M13(GND38) U5.M14(GND50) U5.M16(GND67) U5.M17(GND72) U5.N6(GND12) U5.N10(GND17) U5.N11(GND22) U5.N12(GND29) U5.N13(GND39) U5.N14(GND51) U5.N15(GND61) U5.N16(GND68) U5.N17(GND73) U5.N26(GND89) U5.P1(GND2) U5.P10(GND18) U5.P11(GND23) U5.P12(GND30) U5.P13(GND40) U5.P14(GND52) U5.P15(GND62) U5.P16(GND69) U5.P17(GND74) U5.P21(GND79) U5.R10(GND19) U5.R11(GND24) U5.R13(GND41) U5.R14(GND53) U5.R16(GND70) U5.R17(GND75) U5.T12(GND31) U5.T13(GND42) U5.T14(GND54) U5.T15(GND63) U5.U11(GND25) U5.U12(GND32) U5.U13(GND43) U5.U14(GND55) U5.U15(GND64) U5.U16(GND71) U5.V3(GND10) U5.V13(GND44) U5.V14(GND56) U5.V24(GND82) U5.Y16(VBATT_0) U8.8(GND) U8.15(PAD) U14.2(GND-1) U14.7(GND-2) U14.17(GND-4) U14.23(GND-5) U14.31(GND-6) U14.36(GND-7) U14.46(GND-8) U25.5(VEE) Y2.2(GND) ; also on sheet 3 4 5 6 7 8
VINI+: J7.3 ; also on sheet 3
VINI-: J8.3 ; also on sheet 3
VINQ+: J9.3 ; also on sheet 3
VINQ-: J10.3 ; also on sheet 3
ADC_TDIODE+: C76.2 U8.7(D1+) ; also on sheet 3
ADC_TDIODE-: C75.1 C76.1 U5.G13(TDN_0) U8.5(D-) ; also on sheet 3
B7/ADC_PWR: R58.2 R59.1 U5.AC24(IO_L16N_7)
B7/EXT_TRIG+: R136.2 R137.1 U5.G18(IO_L9P_CC_LC_5)
B7/EXT_TRIG-: R134.2 R135.1 U5.G17(IO_L9N_CC_LC_5)
B7/FLASH_TDO: R43.2 U5.Y12(TDI_0) U14.22(TDO)
B7/JP_1: J18.1 R33.2 U5.AC14(IO_L5P_D7_LC_2)
B7/JP_2: J18.3 R37.2 U5.AD14(IO_L5N_D6_LC_2)
B7/JP_3: J18.5 R36.2 U5.AA12(IO_L6P_D5_LC_2)
B7/JP_4: J18.7 R35.2 U5.AA11(IO_L6N_D4_LC_2)
B7/JP_5: J18.9 R32.2 U5.AC16(IO_L7P_D3_LC_2)
B7/LED_ADC_CAL: ADC_CALIBRATION.2(CATHODE) U5.AE12(IO_L1N_GC_LC_4)
B7/LED_ADC_PWR: ADC_POWER.2(CATHODE) U5.AF12(IO_L1P_GC_LC_4)
B7/LED_DCLK_LOCKED: DCLK_LOCKED.2(CATHODE) U5.AF10(IO_L4N_GC_VREF_LC_4)
B7/LED_ECM_ENA: ECM_ENABLED.2(CATHODE) U5.AD8(IO_L32P_8)
B7/LED_FPGA_OPER: FPGA_OPERATIONAL.2(CATHODE) U5.AF11(IO_L4P_GC_LC_4)
B7/LED_OVERRANGE_I: OVER-RANGE_I-CH.2(CATHODE) U5.AB17(IO_L3P_GC_LC_4)
B7/LED_OVERRANGE_Q: OVER-RANGE_Q-CH.2(CATHODE) U5.AC17(IO_L3N_GC_LC_4)
B7/LED_RCOUT_ENA: RCOUT1/2_ENABLED.2(CATHODE) U5.AC8(IO_L32N_8)
B7/LED_TRIGGER: TRIGGER_ARMED.2(CATHODE) U5.AB10(IO_L2N_GC_LC_4)
B7/SCLK_USI: J15.5 J17.5 U5.F13(IO_L1N_D30_LC_1)
B7/SCS1_USI: J17.3 U5.F14(IO_L1P_D31_LC_1)
B7/SCS2_USI: J15.3 U5.F16(IO_L3P_D27_LC_1)
B7/SDI_USI: J15.7 J17.7 U5.F11(IO_L2N_D28_LC_1)
B7/SDO_USI: J15.4 J17.4 U5.F12(IO_L2P_D29_LC_1)
B7/TCRIT1: R104.2 U5.AC15(IO_L7N_D2_LC_2) U8.10(TCRIT1)
B7/TCRIT2: R87.2 U5.AC13(IO_L8P_D1_LC_2) U8.11(TCRIT2)
B7/TCRIT3: R86.2 U5.AD13(IO_L8N_D0_LC_2) U8.14(TCRIT3)
B7/TEST1N: R30.1 U5.AA13(IO_L4N_D8_VREF_LC_2) U6.3
B7/TEST1P: R30.2 U5.AB13(IO_L4P_D9_LC_2) U6.1
B7/TEST2N: R39.1 U5.AA15(IO_L3N_D10_LC_2) U6.7
B7/TEST2P: R39.2 U5.AA16(IO_L3P_D11_LC_2) U6.5
B7/TEST3N: R41.1 U5.AC11(IO_L2N_D12_LC_2) U7.3
B7/TEST3P: R41.2 U5.AC12(IO_L2P_D13_LC_2) U7.1
B7/TEST4N: R42.1 U5.AB14(IO_L1N_D14_CC_LC_2) U7.7
B7/TEST4P: R42.2 U5.AA14(IO_L1P_D15_CC_LC_2) U7.5
CAL: U5.AD25(IO_L11P_7) ; also on sheet 3
CALDLY: R113.2 ; also on sheet 3
CALRUN: U5.AF23(IO_L19P_7) ; also on sheet 3
CONF_CCLK: R31.1 R81.2 R83.2 R84.1 ; also on sheet 5
CONF_DIN: U5.G12(D_IN_0) U14.28(D0) ; also on sheet 5
CONF_DONE: R29.2 U5.H14(DONE_0) U14.13(~{CE}) ; also on sheet 5
CONF_INITB: R34.2 U5.G15(INIT_B_0) U14.11(OE/~{RST}) ; also on sheet 5
CS_N: U5.AF7(IO_L25N_CC_LC_8) ; also on sheet 5
CY_ADDR0: U5.W2(IO_L1P_8) ; also on sheet 5
CY_ADDR1: U5.W1(IO_L1N_8) ; also on sheet 5
CY_ADDR2: U5.V6(IO_L2P_8) ; also on sheet 5
CY_ADDR3: U5.V5(IO_L2N_8) ; also on sheet 5
CY_ADDR4: U5.W7(IO_L3P_8) ; also on sheet 5
CY_ADDR5: U5.V7(IO_L3N_8) ; also on sheet 5
CY_ADDR6: U5.W4(IO_L4P_8) ; also on sheet 5
CY_ADDR7: U5.W3(IO_L4N_VREF_8) ; also on sheet 5
CY_ADDR8: U5.W6(IO_L5P_8) ; also on sheet 5
CY_ADDR9: U5.W5(IO_L5N_8) ; also on sheet 5
CY_ADDR10: U5.Y2(IO_L6P_8) ; also on sheet 5
CY_ADDR11: U5.Y1(IO_L6N_8) ; also on sheet 5
CY_ADDR12: U5.AA4(IO_L7P_8) ; also on sheet 5
CY_ADDR13: U5.AA3(IO_L7N_8) ; also on sheet 5
CY_ADDR14: U5.Y4(IO_L8P_CC_LC_8) ; also on sheet 5
CY_ADDR15: U5.Y3(IO_L8N_CC_LC_8) ; also on sheet 5
CY_CTL3: U5.AE14(IO_L5P_GC_LC_4) ; also on sheet 5
CY_CTL4: U5.AE13(IO_L5N_GC_LC_4) ; also on sheet 5
CY_CTL5: U5.AE10(IO_L6P_GC_LC_4) ; also on sheet 5
CY_DATA0: U5.AF4(IO_L17P_8) ; also on sheet 5
CY_DATA1: U5.AE4(IO_L17N_8) ; also on sheet 5
CY_DATA2: U5.AD3(IO_L18P_8) ; also on sheet 5
CY_DATA3: U5.AC3(IO_L18N_8) ; also on sheet 5
CY_DATA4: U5.AF6(IO_L19P_8) ; also on sheet 5
CY_DATA5: U5.AF5(IO_L19N_8) ; also on sheet 5
CY_DATA6: U5.AA7(IO_L20P_8) ; also on sheet 5
CY_DATA7: U5.Y7(IO_L20N_VREF_8) ; also on sheet 5
CY_FD0: U5.Y6(IO_L9P_CC_LC_8) ; also on sheet 5
CY_FD1: U5.Y5(IO_L9N_CC_LC_8) ; also on sheet 5
CY_FD2: U5.AB1(IO_L10P_8) ; also on sheet 5
CY_FD3: U5.AA1(IO_L10N_8) ; also on sheet 5
CY_FD4: U5.AC4(IO_L11P_8) ; also on sheet 5
CY_FD5: U5.AB4(IO_L11N_8) ; also on sheet 5
CY_FD6: U5.AB3(IO_L12P_8) ; also on sheet 5
CY_FD7: U5.AB2(IO_L12N_VREF_8) ; also on sheet 5
CY_FD8: U5.AC5(IO_L13P_8) ; also on sheet 5
CY_FD9: U5.AB5(IO_L13N_8) ; also on sheet 5
CY_FD10: U5.AC2(IO_L14P_8) ; also on sheet 5
CY_FD11: U5.AC1(IO_L14N_8) ; also on sheet 5
CY_FD12: U5.AF3(IO_L15P_8) ; also on sheet 5
CY_FD13: U5.AE3(IO_L15N_8) ; also on sheet 5
CY_FD14: U5.AD2(IO_L16P_8) ; also on sheet 5
CY_FD15: U5.AD1(IO_L16N_8) ; also on sheet 5
CY_ID0: U5.AA9(IO_L21P_8) ; also on sheet 5
CY_ID1: U5.Y9(IO_L21N_8) ; also on sheet 5
CY_ID2: U5.AD5(IO_L22P_8) ; also on sheet 5
CY_ID3: U5.AD4(IO_L22N_8) ; also on sheet 5
CY_REQ: U5.AB7(IO_L28N_VREF_8) ; also on sheet 5
CY_VALID: U5.AC9(IO_L29P_8) ; also on sheet 5
DCLKI+: U5.A16(IO_L5P_GC_LC_3) ; also on sheet 3
DCLKI-: U5.A15(IO_L5N_GC_LC_3) ; also on sheet 3
DCLKQ+: U5.A10(IO_L6P_GC_LC_3) ; also on sheet 3
DCLKQ-: U5.B10(IO_L6N_GC_LC_3) ; also on sheet 3
DDRPHASE: R28.2 ; also on sheet 3
DES: R26.2 ; also on sheet 3
DI+0: U5.N23(IO_L16P_9) ; also on sheet 3
DI+1: U5.M21(IO_L13P_9) ; also on sheet 3
DI+2: U5.M23(IO_L14P_9) ; also on sheet 3
DI+3: U5.M25(IO_L11P_9) ; also on sheet 3
DI+4: U5.L21(IO_L6P_9) ; also on sheet 3
DI+5: U5.L24(IO_L10P_9) ; also on sheet 3
DI+6: U5.L26(IO_L12P_9) ; also on sheet 3
DI+7: U5.K22(IO_L3P_9) ; also on sheet 3
DI+8: U5.K24(IO_L7P_9) ; also on sheet 3
DI+9: U5.K26(IO_L8P_CC_LC_9) ; also on sheet 3
DI+10: U5.J21(IO_L1P_9) ; also on sheet 3
DI+11: U5.J23(IO_L2P_9) ; also on sheet 3
DI-0: U5.N22(IO_L16N_9) ; also on sheet 3
DI-1: U5.M20(IO_L13N_9) ; also on sheet 3
DI-2: U5.M22(IO_L14N_9) ; also on sheet 3
DI-3: U5.M24(IO_L11N_9) ; also on sheet 3
DI-4: U5.L20(IO_L6N_9) ; also on sheet 3
DI-5: U5.L23(IO_L10N_9) ; also on sheet 3
DI-6: U5.M26(IO_L12N_VREF_9) ; also on sheet 3
DI-7: U5.K21(IO_L3N_9) ; also on sheet 3
DI-8: U5.K23(IO_L7N_9) ; also on sheet 3
DI-9: U5.K25(IO_L8N_CC_LC_9) ; also on sheet 3
DI-10: U5.J20(IO_L1N_9) ; also on sheet 3
DI-11: U5.J22(IO_L2N_9) ; also on sheet 3
DID+0: U5.V26(IO_L32P_9) ; also on sheet 3
DID+1: U5.U25(IO_L28P_9) ; also on sheet 3
DID+2: U5.T21(IO_L30P_9) ; also on sheet 3
DID+3: U5.T24(IO_L24P_CC_LC_9) ; also on sheet 3
DID+4: U5.T26(IO_L26P_9) ; also on sheet 3
DID+5: U5.R22(IO_L23P_VRN_9) ; also on sheet 3
DID+6: U5.R24(IO_L22P_9) ; also on sheet 3
DID+7: U5.R26(IO_L20P_9) ; also on sheet 3
DID+8: U5.P23(IO_L19P_9) ; also on sheet 3
DID+9: U5.P25(IO_L18P_9) ; also on sheet 3
DID+10: U5.N21(IO_L17P_9) ; also on sheet 3
DID+11: U5.N25(IO_L15P_9) ; also on sheet 3
DID-0: U5.V25(IO_L32N_9) ; also on sheet 3
DID-1: U5.U24(IO_L28N_VREF_9) ; also on sheet 3
DID-2: U5.T20(IO_L30N_9) ; also on sheet 3
DID-3: U5.T23(IO_L24N_CC_LC_9) ; also on sheet 3
DID-4: U5.U26(IO_L26N_9) ; also on sheet 3
DID-5: U5.R21(IO_L23N_VRP_9) ; also on sheet 3
DID-6: U5.R23(IO_L22N_9) ; also on sheet 3
DID-7: U5.R25(IO_L20N_VREF_9) ; also on sheet 3
DID-8: U5.P22(IO_L19N_9) ; also on sheet 3
DID-9: U5.P24(IO_L18N_9) ; also on sheet 3
DID-10: U5.N20(IO_L17N_9) ; also on sheet 3
DID-11: U5.N24(IO_L15N_9) ; also on sheet 3
DQ+0: U5.D26(IO_L25P_CC_LC_5) ; also on sheet 3
DQ+1: U5.F20(IO_L19P_5) ; also on sheet 3
DQ+2: U5.E23(IO_L18P_5) ; also on sheet 3
DQ+3: U5.E25(IO_L27P_5) ; also on sheet 3
DQ+4: U5.G19(IO_L17P_5) ; also on sheet 3
DQ+5: U5.F24(IO_L24P_CC_LC_5) ; also on sheet 3
DQ+6: U5.F26(IO_L29P_5) ; also on sheet 3
DQ+7: U5.G22(IO_L23P_VRN_5) ; also on sheet 3
DQ+8: U5.G24(IO_L28P_5) ; also on sheet 3
DQ+9: U5.G26(IO_L31P_5) ; also on sheet 3
DQ+10: U5.H22(IO_L26P_5) ; also on sheet 3
DQ+11: U5.H24(IO_L30P_5) ; also on sheet 3
DQ-0: U5.D25(IO_L25N_CC_LC_5) ; also on sheet 3
DQ-1: U5.E20(IO_L19N_5) ; also on sheet 3
DQ-2: U5.E22(IO_L18N_5) ; also on sheet 3
DQ-3: U5.E24(IO_L27N_5) ; also on sheet 3
DQ-4: U5.F19(IO_L17N_5) ; also on sheet 3
DQ-5: U5.F23(IO_L24N_CC_LC_5) ; also on sheet 3
DQ-6: U5.E26(IO_L29N_5) ; also on sheet 3
DQ-7: U5.G21(IO_L23N_VRP_5) ; also on sheet 3
DQ-8: U5.G23(IO_L28N_VREF_5) ; also on sheet 3
DQ-9: U5.G25(IO_L31N_5) ; also on sheet 3
DQ-10: U5.H21(IO_L26N_5) ; also on sheet 3
DQ-11: U5.H23(IO_L30N_5) ; also on sheet 3
DQD+0: U5.A20(IO_L13P_5) ; also on sheet 3
DQD+1: U5.A22(IO_L15P_5) ; also on sheet 3
DQD+2: U5.A24(IO_L8P_CC_LC_5) ; also on sheet 3
DQD+3: U5.B24(IO_L10P_5) ; also on sheet 3
DQD+4: U5.C20(IO_L2P_5) ; also on sheet 3
DQD+5: U5.C21(IO_L6P_5) ; also on sheet 3
DQD+6: U5.C26(IO_L20P_5) ; also on sheet 3
DQD+7: U5.D20(IO_L4P_5) ; also on sheet 3
DQD+8: U5.D22(IO_L14P_5) ; also on sheet 3
DQD+9: U5.D23(IO_L21P_5) ; also on sheet 3
DQD+10: U5.D24(IO_L16P_5) ; also on sheet 3
DQD+11: U5.E21(IO_L12P_5) ; also on sheet 3
DQD-0: U5.A19(IO_L13N_5) ; also on sheet 3
DQD-1: U5.A21(IO_L15N_5) ; also on sheet 3
DQD-2: U5.A23(IO_L8N_CC_LC_5) ; also on sheet 3
DQD-3: U5.B23(IO_L10N_5) ; also on sheet 3
DQD-4: U5.B20(IO_L2N_5) ; also on sheet 3
DQD-5: U5.B21(IO_L6N_5) ; also on sheet 3
DQD-6: U5.C25(IO_L20N_VREF_5) ; also on sheet 3
DQD-7: U5.D19(IO_L4N_VREF_5) ; also on sheet 3
DQD-8: U5.C22(IO_L14N_5) ; also on sheet 3
DQD-9: U5.C23(IO_L21N_5) ; also on sheet 3
DQD-10: U5.C24(IO_L16N_5) ; also on sheet 3
DQD-11: U5.D21(IO_L12N_VREF_5) ; also on sheet 3
ECE: R46.2 ; also on sheet 3
FIFOADR0: U5.AC6(IO_L24P_CC_LC_8) ; also on sheet 5
FIFOADR1: U5.AB6(IO_L24N_CC_LC_8) ; also on sheet 5
FLAGA: U5.Y10(IO_L27P_8) ; also on sheet 5
FLAGB: U5.AA10(IO_L27N_8) ; also on sheet 5
FLAGC: U5.AC7(IO_L28P_8) ; also on sheet 5
FMC_CALRUN: U5.H6(IO_L29P_6) ; also on sheet 4
FMC_DCLK_DI+: U5.J2(IO_L4P_10) ; also on sheet 4
FMC_DCLK_DI-: U5.J1(IO_L4N_VREF_10) ; also on sheet 4
FMC_DCLK_DID+: U5.P8(IO_L19P_10) ; also on sheet 4
FMC_DCLK_DID-: U5.N8(IO_L19N_10) ; also on sheet 4
FMC_DCLK_DQ+: U5.H2(IO_L32P_6) ; also on sheet 4
FMC_DCLK_DQ-: U5.H1(IO_L32N_6) ; also on sheet 4
FMC_DCLK_DQD+: U5.A9(IO_L13P_6) ; also on sheet 4
FMC_DCLK_DQD-: U5.B9(IO_L13N_6) ; also on sheet 4
FMC_DI+0: U5.N7(IO_L17P_10) ; also on sheet 4
FMC_DI+1: U5.M6(IO_L13P_10) ; also on sheet 4
FMC_DI+2: U5.N5(IO_L15P_10) ; also on sheet 4
FMC_DI+3: U5.M4(IO_L12P_10) ; also on sheet 4
FMC_DI+4: U5.N3(IO_L14P_10) ; also on sheet 4
FMC_DI+5: U5.M2(IO_L11P_10) ; also on sheet 4
FMC_DI+6: U5.L7(IO_L5P_10) ; also on sheet 4
FMC_DI+7: U5.K7(IO_L3P_10) ; also on sheet 4
FMC_DI+8: U5.K5(IO_L6P_10) ; also on sheet 4
FMC_DI+9: U5.J5(IO_L2P_10) ; also on sheet 4
FMC_DI+10: U5.L1(IO_L10P_10) ; also on sheet 4
FMC_DI+11: U5.K3(IO_L7P_10) ; also on sheet 4
FMC_DI-0: U5.M7(IO_L17N_10) ; also on sheet 4
FMC_DI-1: U5.M5(IO_L13N_10) ; also on sheet 4
FMC_DI-2: U5.N4(IO_L15N_10) ; also on sheet 4
FMC_DI-3: U5.M3(IO_L12N_VREF_10) ; also on sheet 4
FMC_DI-4: U5.N2(IO_L14N_10) ; also on sheet 4
FMC_DI-5: U5.M1(IO_L11N_10) ; also on sheet 4
FMC_DI-6: U5.L6(IO_L5N_10) ; also on sheet 4
FMC_DI-7: U5.K6(IO_L3N_10) ; also on sheet 4
FMC_DI-8: U5.K4(IO_L6N_10) ; also on sheet 4
FMC_DI-9: U5.J4(IO_L2N_10) ; also on sheet 4
FMC_DI-10: U5.K1(IO_L10N_10) ; also on sheet 4
FMC_DI-11: U5.K2(IO_L7N_10) ; also on sheet 4
FMC_DID+0: U5.T8(IO_L31P_10) ; also on sheet 4
FMC_DID+1: U5.T7(IO_L27P_10) ; also on sheet 4
FMC_DID+2: U5.U6(IO_L32P_10) ; also on sheet 4
FMC_DID+3: U5.V4(IO_L29P_10) ; also on sheet 4
FMC_DID+4: U5.T4(IO_L26P_10) ; also on sheet 4
FMC_DID+5: U5.U3(IO_L28P_10) ; also on sheet 4
FMC_DID+6: U5.V2(IO_L30P_10) ; also on sheet 4
FMC_DID+7: U5.P7(IO_L21P_10) ; also on sheet 4
FMC_DID+8: U5.R4(IO_L20P_10) ; also on sheet 4
FMC_DID+9: U5.R2(IO_L22P_10) ; also on sheet 4
FMC_DID+10: U5.P5(IO_L18P_10) ; also on sheet 4
FMC_DID+11: U5.P3(IO_L16P_10) ; also on sheet 4
FMC_DID-0: U5.U7(IO_L31N_10) ; also on sheet 4
FMC_DID-1: U5.T6(IO_L27N_10) ; also on sheet 4
FMC_DID-2: U5.U5(IO_L32N_10) ; also on sheet 4
FMC_DID-3: U5.U4(IO_L29N_10) ; also on sheet 4
FMC_DID-4: U5.T3(IO_L26N_10) ; also on sheet 4
FMC_DID-5: U5.U2(IO_L28N_VREF_10) ; also on sheet 4
FMC_DID-6: U5.V1(IO_L30N_10) ; also on sheet 4
FMC_DID-7: U5.P6(IO_L21N_10) ; also on sheet 4
FMC_DID-8: U5.R3(IO_L20N_VREF_10) ; also on sheet 4
FMC_DID-9: U5.R1(IO_L22N_10) ; also on sheet 4
FMC_DID-10: U5.P4(IO_L18N_10) ; also on sheet 4
FMC_DID-11: U5.P2(IO_L16N_10) ; also on sheet 4
FMC_DQ+0: U5.C4(IO_L16P_6) ; also on sheet 4
FMC_DQ+1: U5.C5(IO_L12P_6) ; also on sheet 4
FMC_DQ+2: U5.E6(IO_L18P_6) ; also on sheet 4
FMC_DQ+3: U5.G6(IO_L23P_VRN_6) ; also on sheet 4
FMC_DQ+4: U5.D3(IO_L22P_6) ; also on sheet 4
FMC_DQ+5: U5.C2(IO_L20P_6) ; also on sheet 4
FMC_DQ+6: U5.F4(IO_L27P_6) ; also on sheet 4
FMC_DQ+7: U5.G4(IO_L28P_6) ; also on sheet 4
FMC_DQ+8: U5.E1(IO_L26P_6) ; also on sheet 4
FMC_DQ+9: U5.D10(IO_L1P_6) ; also on sheet 4
FMC_DQ+10: U5.G2(IO_L30P_6) ; also on sheet 4
FMC_DQ+11: U5.H4(IO_L31P_6) ; also on sheet 4
FMC_DQ-0: U5.D4(IO_L16N_6) ; also on sheet 4
FMC_DQ-1: U5.D5(IO_L12N_VREF_6) ; also on sheet 4
FMC_DQ-2: U5.E5(IO_L18N_6) ; also on sheet 4
FMC_DQ-3: U5.G5(IO_L23N_VRP_6) ; also on sheet 4
FMC_DQ-4: U5.E4(IO_L22N_6) ; also on sheet 4
FMC_DQ-5: U5.C1(IO_L20N_VREF_6) ; also on sheet 4
FMC_DQ-6: U5.F3(IO_L27N_6) ; also on sheet 4
FMC_DQ-7: U5.G3(IO_L28N_VREF_6) ; also on sheet 4
FMC_DQ-8: U5.F1(IO_L26N_6) ; also on sheet 4
FMC_DQ-9: U5.C10(IO_L1N_6) ; also on sheet 4
FMC_DQ-10: U5.G1(IO_L30N_6) ; also on sheet 4
FMC_DQ-11: U5.H3(IO_L31N_6) ; also on sheet 4
FMC_DQD+0: U5.F10(IO_L5P_6) ; also on sheet 4
FMC_DQD+1: U5.E9(IO_L7P_6) ; also on sheet 4
FMC_DQD+2: U5.F8(IO_L10P_6) ; also on sheet 4
FMC_DQD+3: U5.D9(IO_L2P_6) ; also on sheet 4
FMC_DQD+4: U5.D8(IO_L4P_6) ; also on sheet 4
FMC_DQD+5: U5.B7(IO_L11P_6) ; also on sheet 4
FMC_DQD+6: U5.A8(IO_L3P_6) ; also on sheet 4
FMC_DQD+7: U5.F7(IO_L19P_6) ; also on sheet 4
FMC_DQD+8: U5.E7(IO_L17P_6) ; also on sheet 4
FMC_DQD+9: U5.A6(IO_L6P_6) ; also on sheet 4
FMC_DQD+10: U5.A4(IO_L15P_6) ; also on sheet 4
FMC_DQD+11: U5.A3(IO_L14P_6) ; also on sheet 4
FMC_DQD-0: U5.E10(IO_L5N_6) ; also on sheet 4
FMC_DQD-1: U5.F9(IO_L7N_6) ; also on sheet 4
FMC_DQD-2: U5.G8(IO_L10N_6) ; also on sheet 4
FMC_DQD-3: U5.C8(IO_L2N_6) ; also on sheet 4
FMC_DQD-4: U5.D7(IO_L4N_VREF_6) ; also on sheet 4
FMC_DQD-5: U5.C7(IO_L11N_6) ; also on sheet 4
FMC_DQD-6: U5.A7(IO_L3N_6) ; also on sheet 4
FMC_DQD-7: U5.G7(IO_L19N_6) ; also on sheet 4
FMC_DQD-8: U5.D6(IO_L17N_6) ; also on sheet 4
FMC_DQD-9: U5.A5(IO_L6N_6) ; also on sheet 4
FMC_DQD-10: U5.B4(IO_L15N_6) ; also on sheet 4
FMC_DQD-11: U5.B3(IO_L14N_6) ; also on sheet 4
FMC_ORI+: U5.J7(IO_L1P_10) ; also on sheet 4
FMC_ORI-: U5.J6(IO_L1N_10) ; also on sheet 4
FMC_ORQ+: U5.H8(IO_L21P_6) ; also on sheet 4
FMC_ORQ-: U5.H7(IO_L21N_6) ; also on sheet 4
FMC_PG_C2M: U5.R5(IO_L23N_VRP_10) ; also on sheet 4
FMC_PG_M2C: U5.R6(IO_L23P_VRN_10) ; also on sheet 4
FMC_RCOUT1+: U5.U23(IO_L27P_9) ; also on sheet 4
FMC_RCOUT1-: U5.V23(IO_L27N_9) ; also on sheet 4
FMC_RCOUT2+: U5.U22(IO_L29P_9) ; also on sheet 4
FMC_RCOUT2-: U5.U21(IO_L29N_9) ; also on sheet 4
FPGA_RESET: U5.AF8(IO_L25P_CC_LC_8) ; also on sheet 5
FSR: R27.2 ; also on sheet 3
IFCLK: U5.AC10(IO_L2P_GC_LC_4) ; also on sheet 5
LOAD_STATE: U5.AE7(IO_L23P_VRN_8) ; also on sheet 5
NDM: U5.AF21(IO_L30P_SM3_7) ; also on sheet 3
ORI+: U5.J26(IO_L4P_9) ; also on sheet 3
ORI-: U5.J25(IO_L4N_VREF_9) ; also on sheet 3
ORQ+: U5.H26(IO_L32P_5) ; also on sheet 3
ORQ-: U5.H25(IO_L32N_5) ; also on sheet 3
PDI: R44.2 ; also on sheet 3
PDQ: R45.2 ; also on sheet 3
PKTEND: U5.AE9(IO_L31N_8) ; also on sheet 5
PLL_CE: U5.C17(IO_L1P_5) ; also on sheet 8
PLL_LD: U5.H5(IO_L29N_6) ; also on sheet 8
PLL_LE: U5.D17(IO_L1N_5) ; also on sheet 8
PLL_SCLK: U5.G9(IO_L9N_CC_LC_6) ; also on sheet 8
PLL_SDATA: U5.G10(IO_L9P_CC_LC_6) ; also on sheet 8
PROGRAMB: R85.2 U5.H15(PROG_B_0) U14.6(~{CF}) ; also on sheet 5
RCOUT1+: U5.B17(IO_L7P_GC_LC_3) ; also on sheet 3
RCOUT1-: U5.A17(IO_L7N_GC_LC_3) ; also on sheet 3
RCOUT2+: U5.C13(IO_L8P_GC_LC_3) ; also on sheet 3
RCOUT2-: U5.C12(IO_L8N_GC_LC_3) ; also on sheet 3
RD_N: U5.Y8(IO_L26N_8) ; also on sheet 5
SCL_FROM_CY: J15.8 J17.8 U8.13(SMBCLK) ; also on sheet 5
SCLK: U5.AE24(IO_L22N_7) ; also on sheet 3
SCS: U5.AF24(IO_L22P_7) ; also on sheet 3
SDA_FROM_CY: J15.6 J17.6 U8.12(SMBDAT) ; also on sheet 5
SDI: U5.AF22(IO_L30N_SM3_7) ; also on sheet 3
SDO: U5.AF18(IO_L31P_SM2_7) ; also on sheet 3
SLCS_N: U5.AB9(IO_L29N_8) ; also on sheet 5
SLOE: U5.AF9(IO_L31P_8) ; also on sheet 5
SLRD: U5.AE6(IO_L30P_8) ; also on sheet 5
SLWR: U5.AD6(IO_L30N_8) ; also on sheet 5
STATE0: U5.AD10(IO_L6N_GC_LC_4) ; also on sheet 5
STATE1: U5.AD17(IO_L7P_GC_VRN_LC_4) ; also on sheet 5
STATE2: U5.AD16(IO_L7N_GC_VRP_LC_4) ; also on sheet 5
STATE3: U5.AD11(IO_L8N_GC_CC_LC_4) ; also on sheet 5
TPM: R114.2 ; also on sheet 3
V_ADC: C365.2 R58.1 ; also on sheet 3 6
V_USI1: J15.2 J17.2 ; also on sheet 6
VCMO: J15.9 J17.9 ; also on sheet 3
WE_N: U5.AA8(IO_L26P_8) ; also on sheet 5
B6/N16663533: J27.3 J28.3
B6/N16663537: J29.3 J30.3
B6/N16663541: J31.3 J32.3
B7/N16802160: R40.2 U5.G16(HSWAPEN_0)
B7/N16802193: C75.2 U5.H13(TDP_0) U8.6(D2+)
B7/N16802234: R31.2 U5.G14(CCLK_0)
B7/N16802239: R38.2 U5.W14(M2_0) U5.W15(M0_0) U5.Y15(M1_0)
B7/N16805320: R53.1 Y2.3(OUT)
B7/N20455301: R83.3 U14.12(CLK)
B7/N20455532: R83.1 U14.9(CLKOUT)
B7/N21058732: R44.1 U5.AD19(IO_L25P_CC_SM7_LC_7)
B7/N21059382: R45.1 U5.AC19(IO_L25N_CC_SM7_LC_7)
B7/N21060033: R46.1 U5.AA19(IO_L26P_SM6_7)
B7/N21060685: R26.1 U5.AA20(IO_L26N_SM6_7)
B7/N21061338: R27.1 U5.Y17(IO_L27P_SM5_7)
B7/N21061992: R28.1 U5.AA17(IO_L27N_SM5_7)
B7/N21062647: R113.1 U5.AB20(IO_L28P_7)
B7/N21063303: R114.1 U5.AC20(IO_L28N_VREF_7)
B7/N21827542: R136.1 U25.7(Q+)
B7/N21827567: R134.1 U25.6(Q-)
B7/N21827581: J26.3 U25.2(D+)
B7/N21832116: U25.3(D-) U25.4(VBB)
B7/N21933562: R126.1 U8.9(A0)
B7/N23828730: R53.2 U5.AD12(IO_L8P_GC_CC_LC_4)
N24212023: FPGA_OPERATIONAL.1(ANODE) R52.1
N24212024: R49.1 TRIGGER_ARMED.1(ANODE)
N24212025: ADC_CALIBRATION.1(ANODE) R48.1
N24212026: ECM_ENABLED.1(ANODE) R55.1
N24212028: R115.1 RCOUT1/2_ENABLED.1(ANODE)
N24212029: DCLK_LOCKED.1(ANODE) R54.1
N24212032: ADC_POWER.1(ANODE) R47.1
N24212033: OVER-RANGE_Q-CH.1(ANODE) R51.1
N24212034: OVER-RANGE_I-CH.1(ANODE) R50.1

Not connected (* = marked no-connect by the designer): J15 10*; J17 10*; U5 A11(IO_L2N_GC_VRP_LC_3)* A12(IO_L2P_GC_VRN_LC_3)* A18(IO_L3N_5)* AA18(IO_L21P_7)* AA23(IO_L14N_7)* AA24(IO_L8P_CC_LC_7)* AA26(IO_L10N_7)* AB18(IO_L29N_SM4_7)* AB21(IO_L24N_CC_LC_7)* AB22(IO_L13N_7)* AB23(IO_L14P_7)* AB24(IO_L7P_7) AB25(IO_L7N_7)* AB26(IO_L10P_7)* AC18(IO_L29P_SM4_7)* AC21(IO_L24P_CC_LC_7)* AC22(IO_L13P_7) AC23(IO_L16P_7)* AC25(IO_L9P_CC_LC_7)* AC26(IO_L9N_CC_LC_7)* AD7(IO_L23N_VRP_8) AD20(IO_L23N_VRP_7)* AD21(IO_L32N_SM1_7)* AD22(IO_L15P_7)* AD23(IO_L15N_7)* AD26(IO_L11N_7)* AE18(IO_L31N_SM2_7)* AE20(IO_L23P_VRN_7)* AE21(IO_L32P_SM1_7)* AE23(IO_L19N_7)* AF19(IO_L17P_7) AF20(IO_L17N_7)* B6(IO_L8P_CC_LC_6)* B12(IO_L4N_GC_VREF_LC_3)* B13(IO_L4P_GC_LC_3)* B14(IO_L1N_GC_CC_LC_3)* B15(IO_L1P_GC_CC_LC_3)* B18(IO_L3P_5)* C6(IO_L8N_CC_LC_6)* C11(IO_L6P_D21_LC_1)* C14(IO_L3N_GC_LC_3)* C15(IO_L3P_GC_LC_3)* C16(IO_L7N_D18_LC_1)* C19(IO_L7P_5)* D1(IO_L25N_CC_LC_6)* D2(IO_L25P_CC_LC_6)* D11(IO_L6N_D20_LC_1)* D12(IO_L8N_D16_CC_LC_1)* D13(IO_L4N_D24_VREF_LC_1)* D14(IO_L4P_D25_LC_1)* D15(IO_L5P_D23_LC_1)* D16(IO_L7P_D19_LC_1)* D18(IO_L7N_5)* E2(IO_L24N_CC_LC_6)* E3(IO_L24P_CC_LC_6)* E13(IO_L8P_D17_CC_LC_1)* E14(IO_L5N_D22_LC_1)* E17(IO_L5P_5)* E18(IO_L11N_5)* F15(IO_L3N_D26_LC_1)* F17(IO_L5N_5)* F18(IO_L11P_5)* G11(CS_B_0)* G20(IO_L22N_5)* H12(RDWR_B_0)* H20(IO_L22P_5)* K20(IO_L5N_9)* L3(IO_L8N_CC_LC_10)* L4(IO_L8P_CC_LC_10)* L8(IO_L9N_CC_LC_10)* L19(IO_L5P_9)* M8(IO_L9P_CC_LC_10)* M19(IO_L9P_CC_LC_9)* N19(IO_L9N_CC_LC_9)* P19(IO_L21N_9)* P20(IO_L21P_9)* R7(IO_L25N_CC_LC_10)* R8(IO_L25P_CC_LC_10)* R19(IO_L25N_CC_LC_9)* R20(IO_L25P_CC_LC_9)* T1(IO_L24N_CC_LC_10)* T19(IO_L31N_9)* U1(IO_L24P_CC_LC_10)* U20(IO_L31P_9)* V20(IO_L5N_7)* V21(IO_L1P_7)* V22(IO_L1N_7)* W13(PWRDWN_B_0)* W19(IO_L18N_7)* W20(IO_L5P_7)* W21(IO_L3P_7)* W22(IO_L3N_7)* W23(IO_L4P_7)* W24(IO_L4N_VREF_7)* W25(IO_L2P_7)* W26(IO_L2N_7)* Y14(DOUT_BUSY_0)* Y18(IO_L21N_7)* Y19(IO_L18P_7)* Y20(IO_L20P_7)* Y21(IO_L20N_VREF_7)* Y22(IO_L12P_7)* Y23(IO_L12N_VREF_7)* Y24(IO_L8N_CC_LC_7)* Y25(IO_L6P_7)* Y26(IO_L6N_7)*; U6 2* 4* 6*; U7 2* 4* 6*; U8 1(NC1)* 3(NC2)* 4(NC3)*; U14 1(DNC-1)* 3(DNC-2)* 5(BUSY)* 10(~{CEO})* 14(DNC-3)* 16(DNC-4)* 18(DNC-5)* 25(~{EN_XSEL})* 26(RV_SEL0)* 27(RV_SEL1)* 29(D1)* 32(D2)* 33(D3)* 35(DNC-6)* 37(DNC-7)* 39(DNC-8)* 40(DNC-9)* 41(DNC-10)* 42(DNC-11)* 43(D4)* 44(D5)* 47(D6)* 48(D7)*; U25 1(NC)*; Y2 1(OE)*

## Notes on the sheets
sheet 9
- BANK 3 - 2.5V LVDS (GCLK)
- BANK 9 - 2.5 V I/O (LVDS)
- BANK 5 - 2.5 V I/O (LVDS)
- BANK 7 - 1.8 V I/O
- BANK 8 - 3.3 V I/O
- BANK 6 - 2.5V I/O
sheet 10
- TEST HEADERS
- SLAVE SERIAL
- MASTER SERIAL
- FIT R43 IF
  CONFIG
  FLASH NOT
  INSTALLED
- JTAG HEADER
- TEST INPUTS
- BANK 10 - 2.5V I/O
- Place C75 and C76 close to LM95233
- BANK 2 - 2.5V I/O
- TEMP SENSOR
- DO NOT FIT V4
  CONFIG FLASH IF
  CYPRESS USB
  CONTROLLER IS
  INSTALLED
- BANK 1 - 2.5 V I/O
- SLAVE
  SERIAL
- MASTER
  SERIAL
- BANK 4 - 3.3 V I/O
- USI-1 HEADER #1
- 100MHZ FPGA CLOCK REF
- USI-1 HEADER #2
- ACTIVE LOW
sheet 11
- BANK0
- BANK1
- BANK2
- BANK3
- BANK4
- BANK #
- BANK SUPPLY
- INTERFACE
- 1
  2
  3
  4
  5
  6
  7
  8
  9
  10
- 2V5IO
  2V5IO
  2V5IO
  3V3IO
  2V5IO
  2V5IO
  1V8IO
  3V3IO
  2V5IO
  2V5IO
- USI-1 Header
  Test Headers, Temp. Sensor
  ADC DCLK
  Cypress, LEDs, 100 MHz oscillator
  ADC Q-Channel (LVDS)
  Clock generator
  ADC Control
  Cypress, LEDs
  ADC I-Channel (LVDS)
  Logic Analyzer Header
- V12
- J15
- E11
- E16
- AB11
- AB16
- B11
- B16
- AE11
- AD15
- BANK5
- H18
- B19
- E19
- H19
- J19
- B22
- F22
- F25
- BANK6
- M9
- N9
- W10
- H11
- W11
- J12
- V15
- P9
- F2
- B5
- F5
- B8
- E8
- J8
- H9
- H10
- BANK7
- H16
- W16
- N18
- H17
- W17
- W18
- V19
- AB19
- AE19
- AA22
- AA25
- AE22
- BANK8
- P18
- R18
- AA2
- AA5
- AE5
- V8
- W8
- AB8
- AE8
- W9
- BANK9
- M18
- K19
- U19
- L22
- T22
- L25
- T25
- P26
- BANK10
- AVDD_SM
- N1
- L2
- T2
- L5
- T5
- K8
- U8
- R9
- AF17
- 1V2VCC_INT
- K9
- L9
- T9
- U9
- J10
- U10
- V10
- J11
- L10
- L10
- T10
- T10
- K10
- V11
- L11
- T11
- M12
- R12
- M15
- R15
- J16
- L16
- T16
- V16
- J17
- K17
- L17
- T17
- U17
- V17
- L18
- T18
- K18
- U18
- U18
sheet 12
- Impedance test connectors
- 50 Ohms
- 100 Ohms
